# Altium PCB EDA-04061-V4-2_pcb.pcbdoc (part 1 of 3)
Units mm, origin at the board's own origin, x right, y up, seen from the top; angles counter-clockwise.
Board outline 105 x 56 mm, 6 copper layers (Top Layer, L2, L3, L4, L5, Bottom Layer), stack 1.58 mm thick; 213 components, 137 nets, 766 pads, 477 vias.
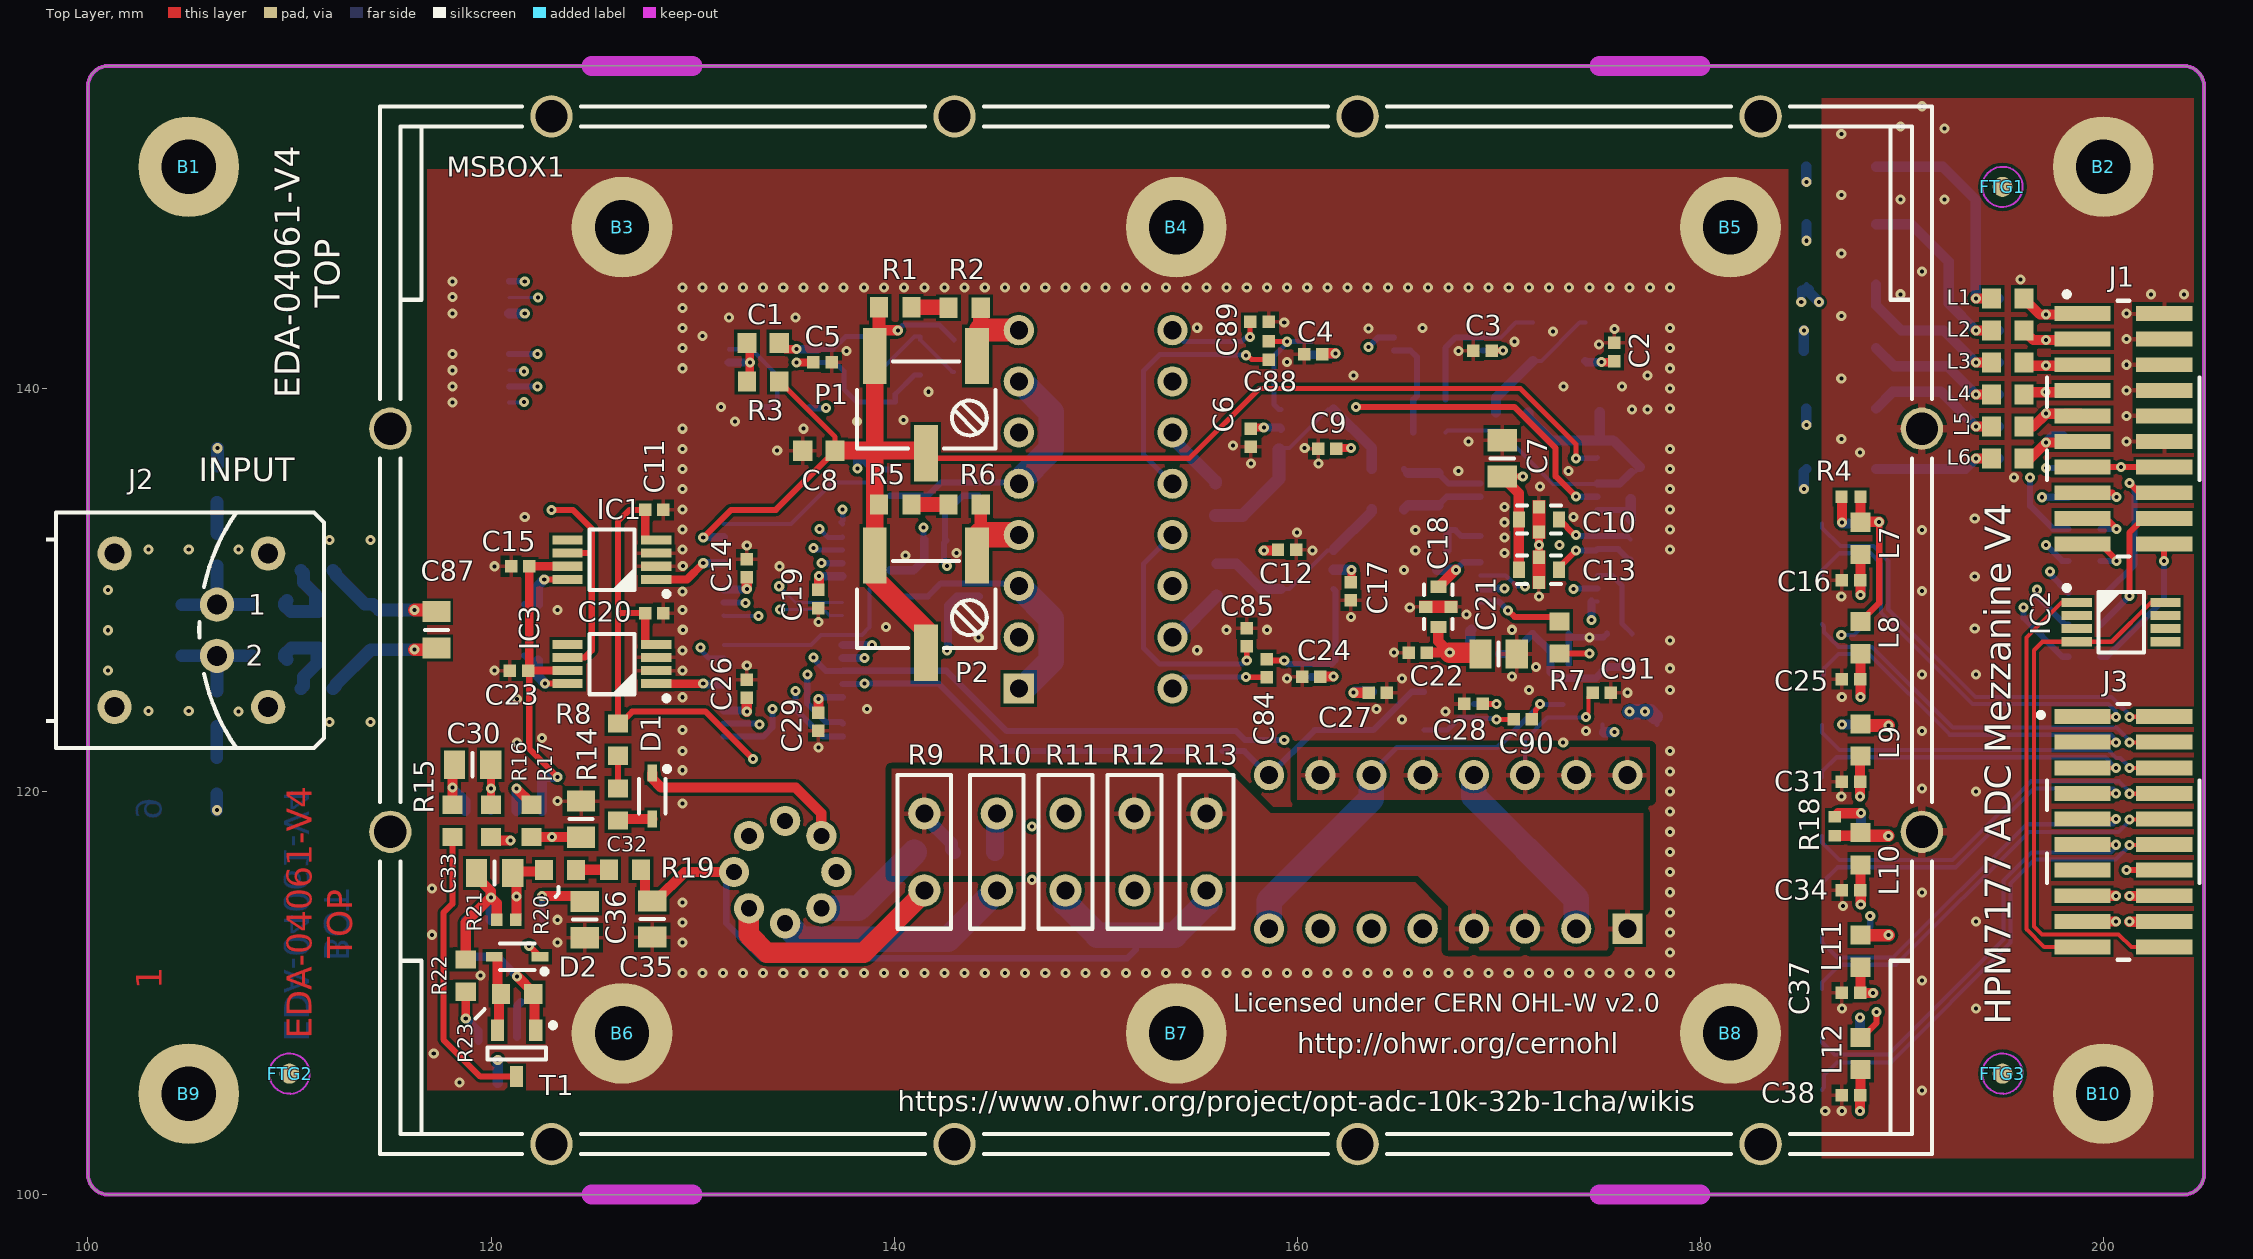
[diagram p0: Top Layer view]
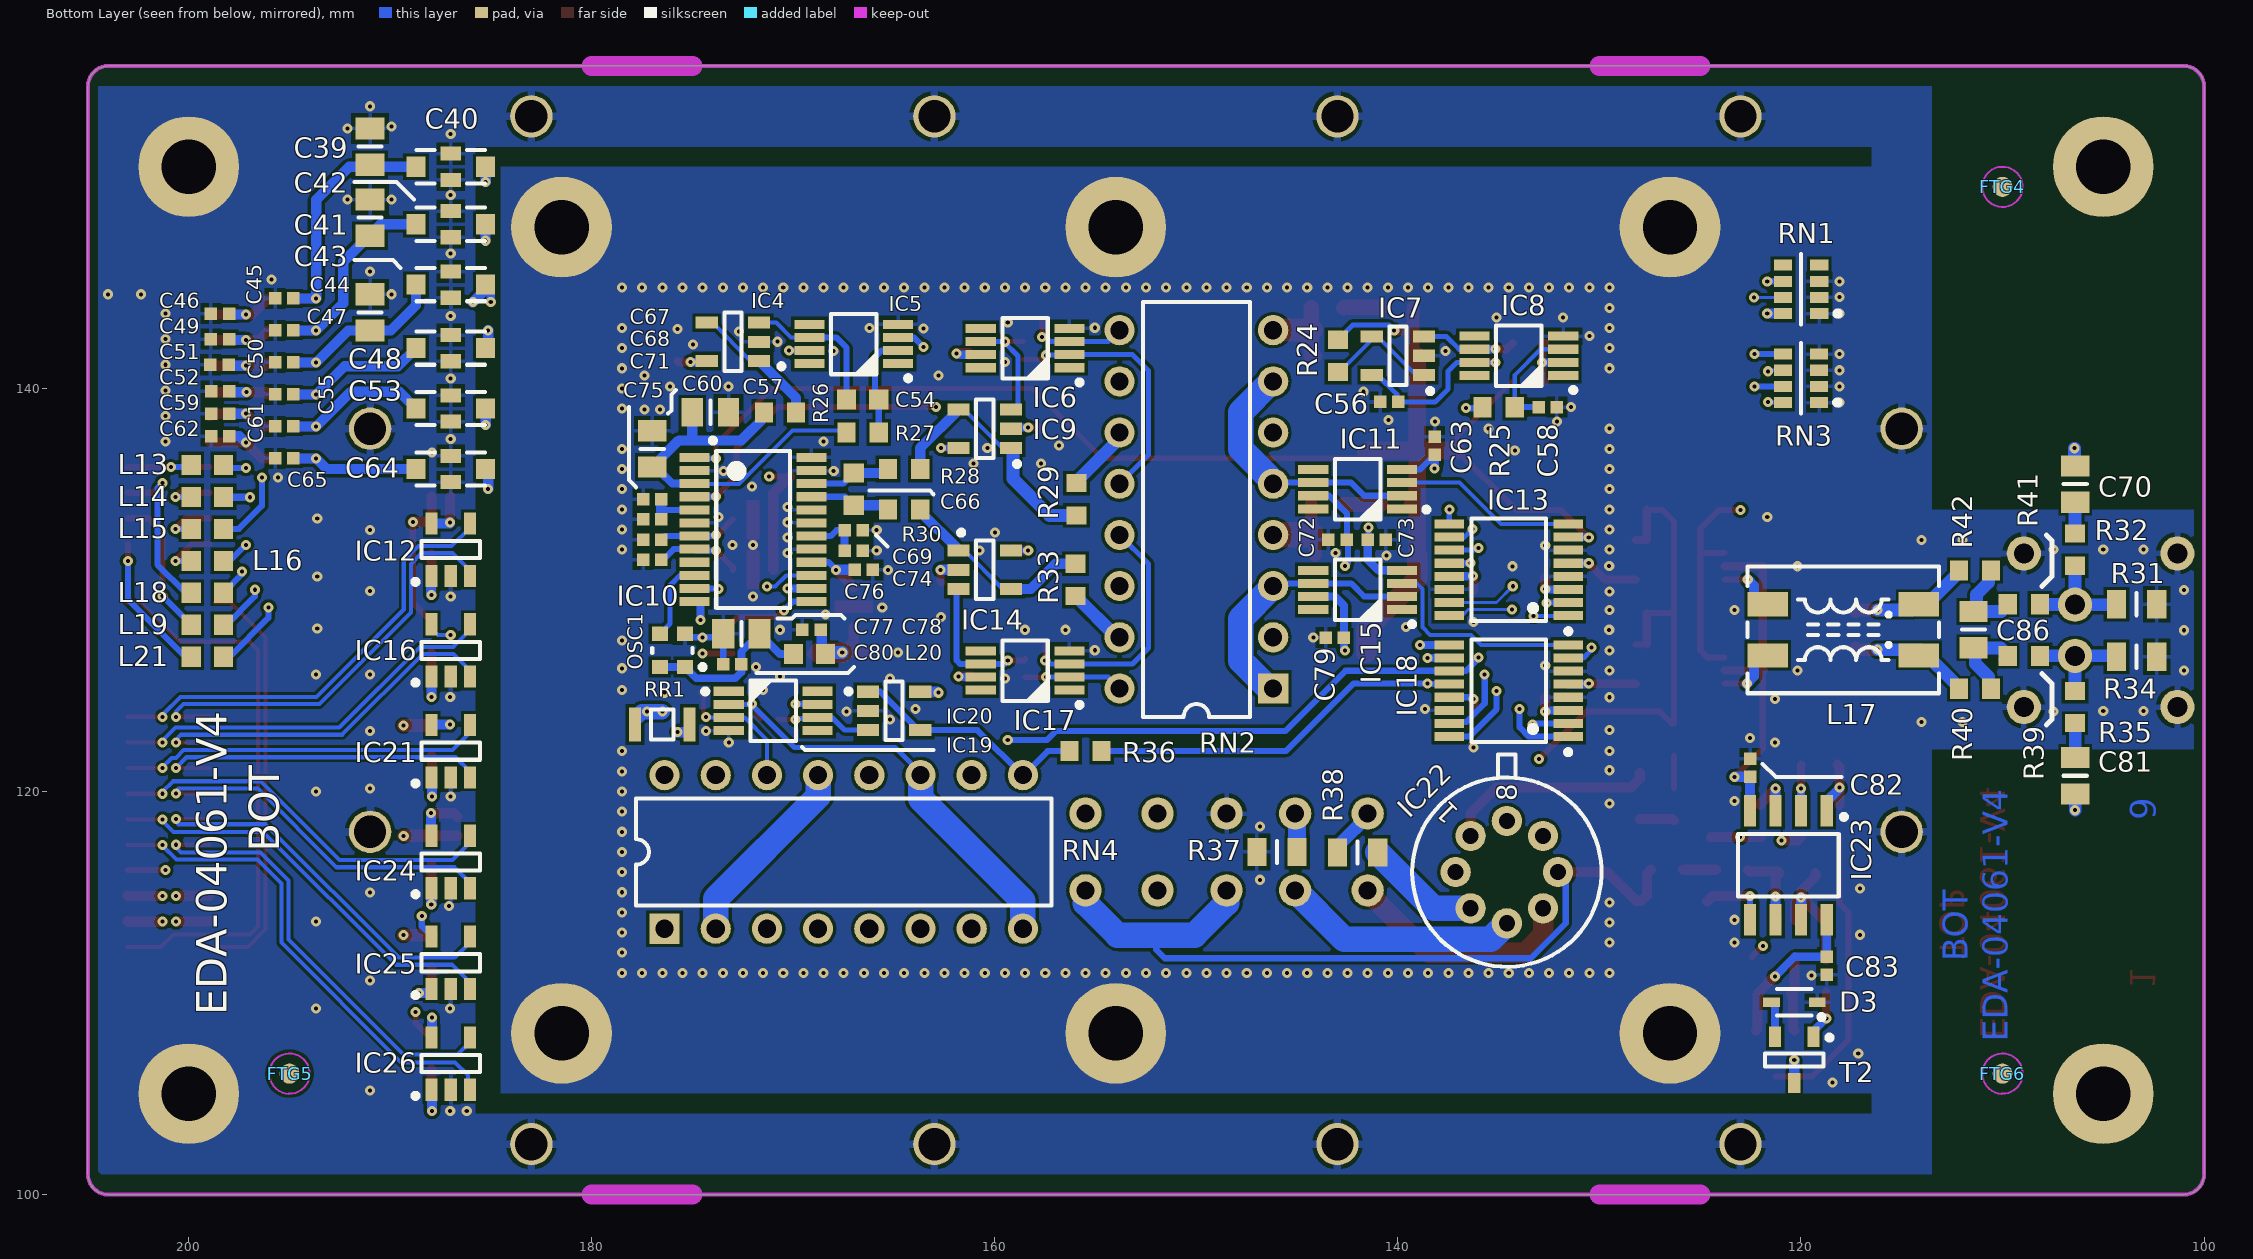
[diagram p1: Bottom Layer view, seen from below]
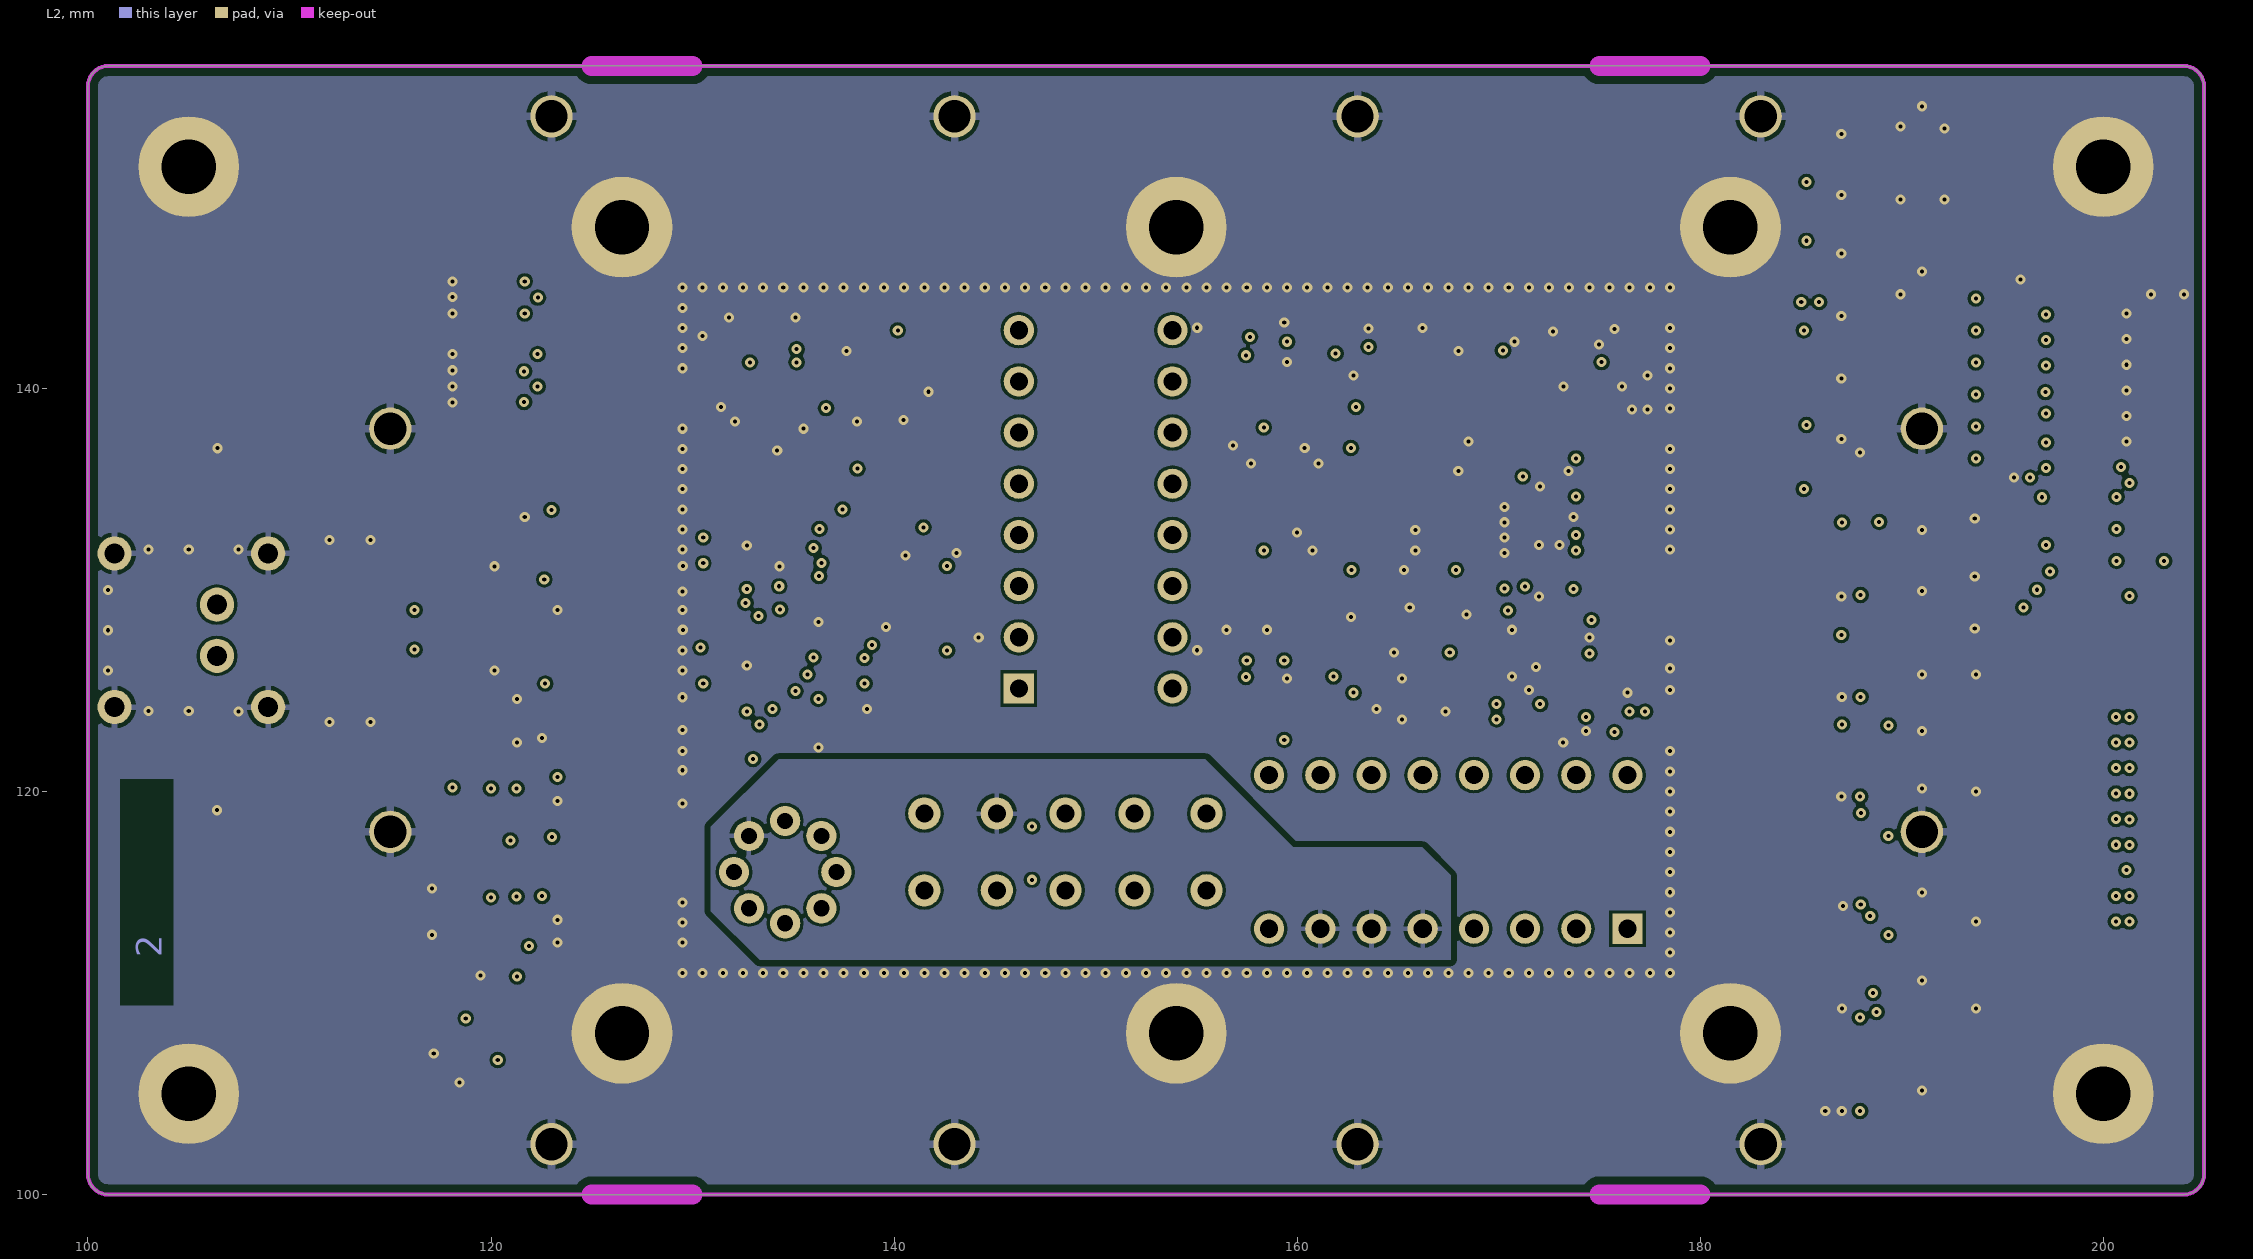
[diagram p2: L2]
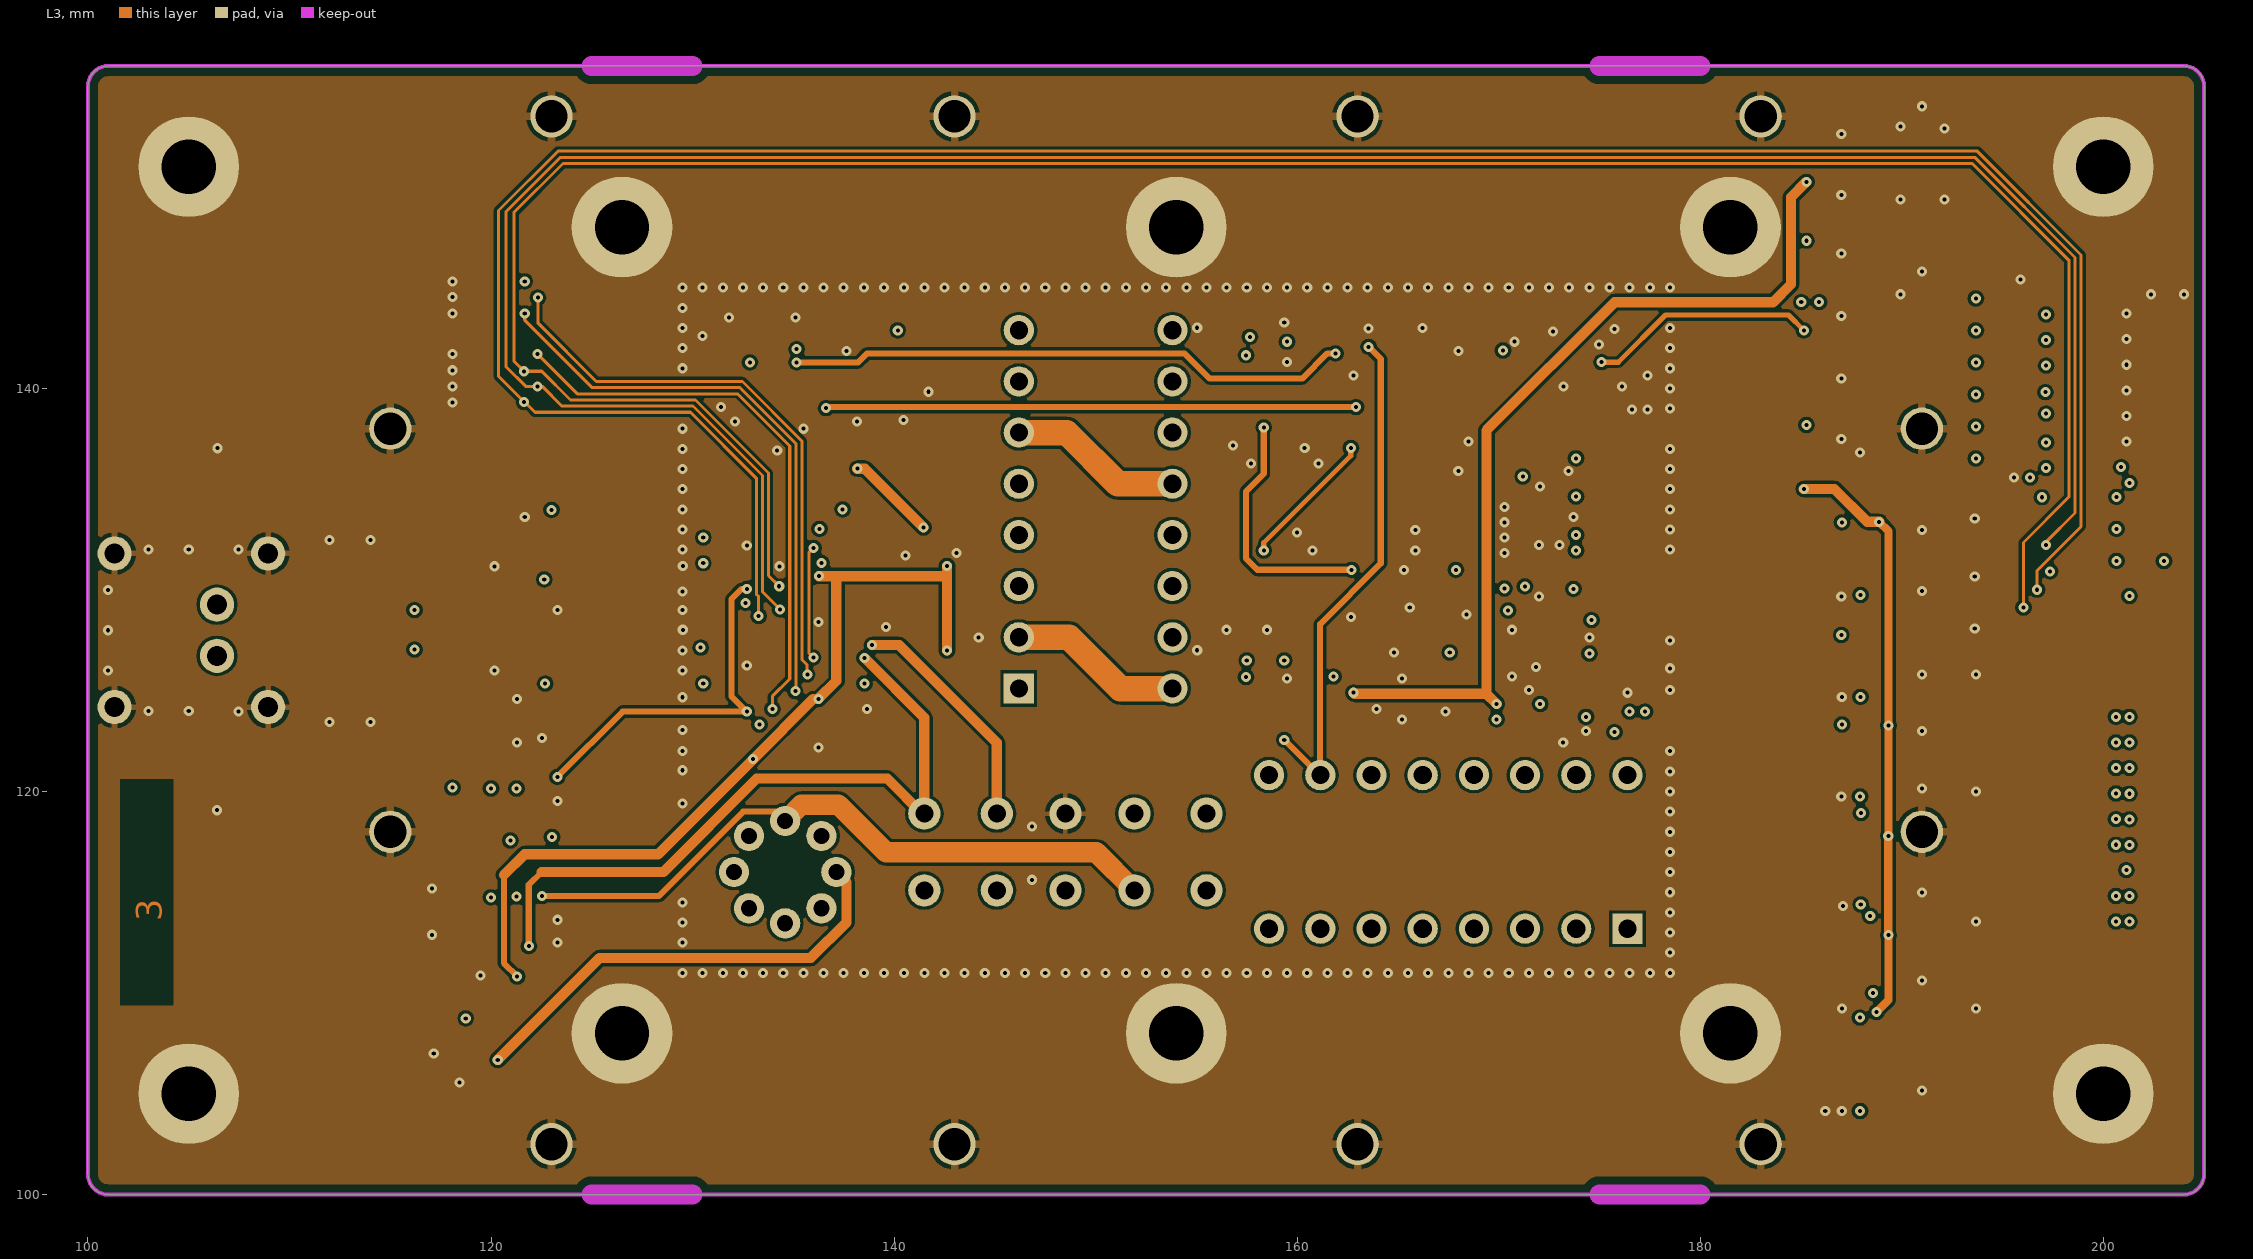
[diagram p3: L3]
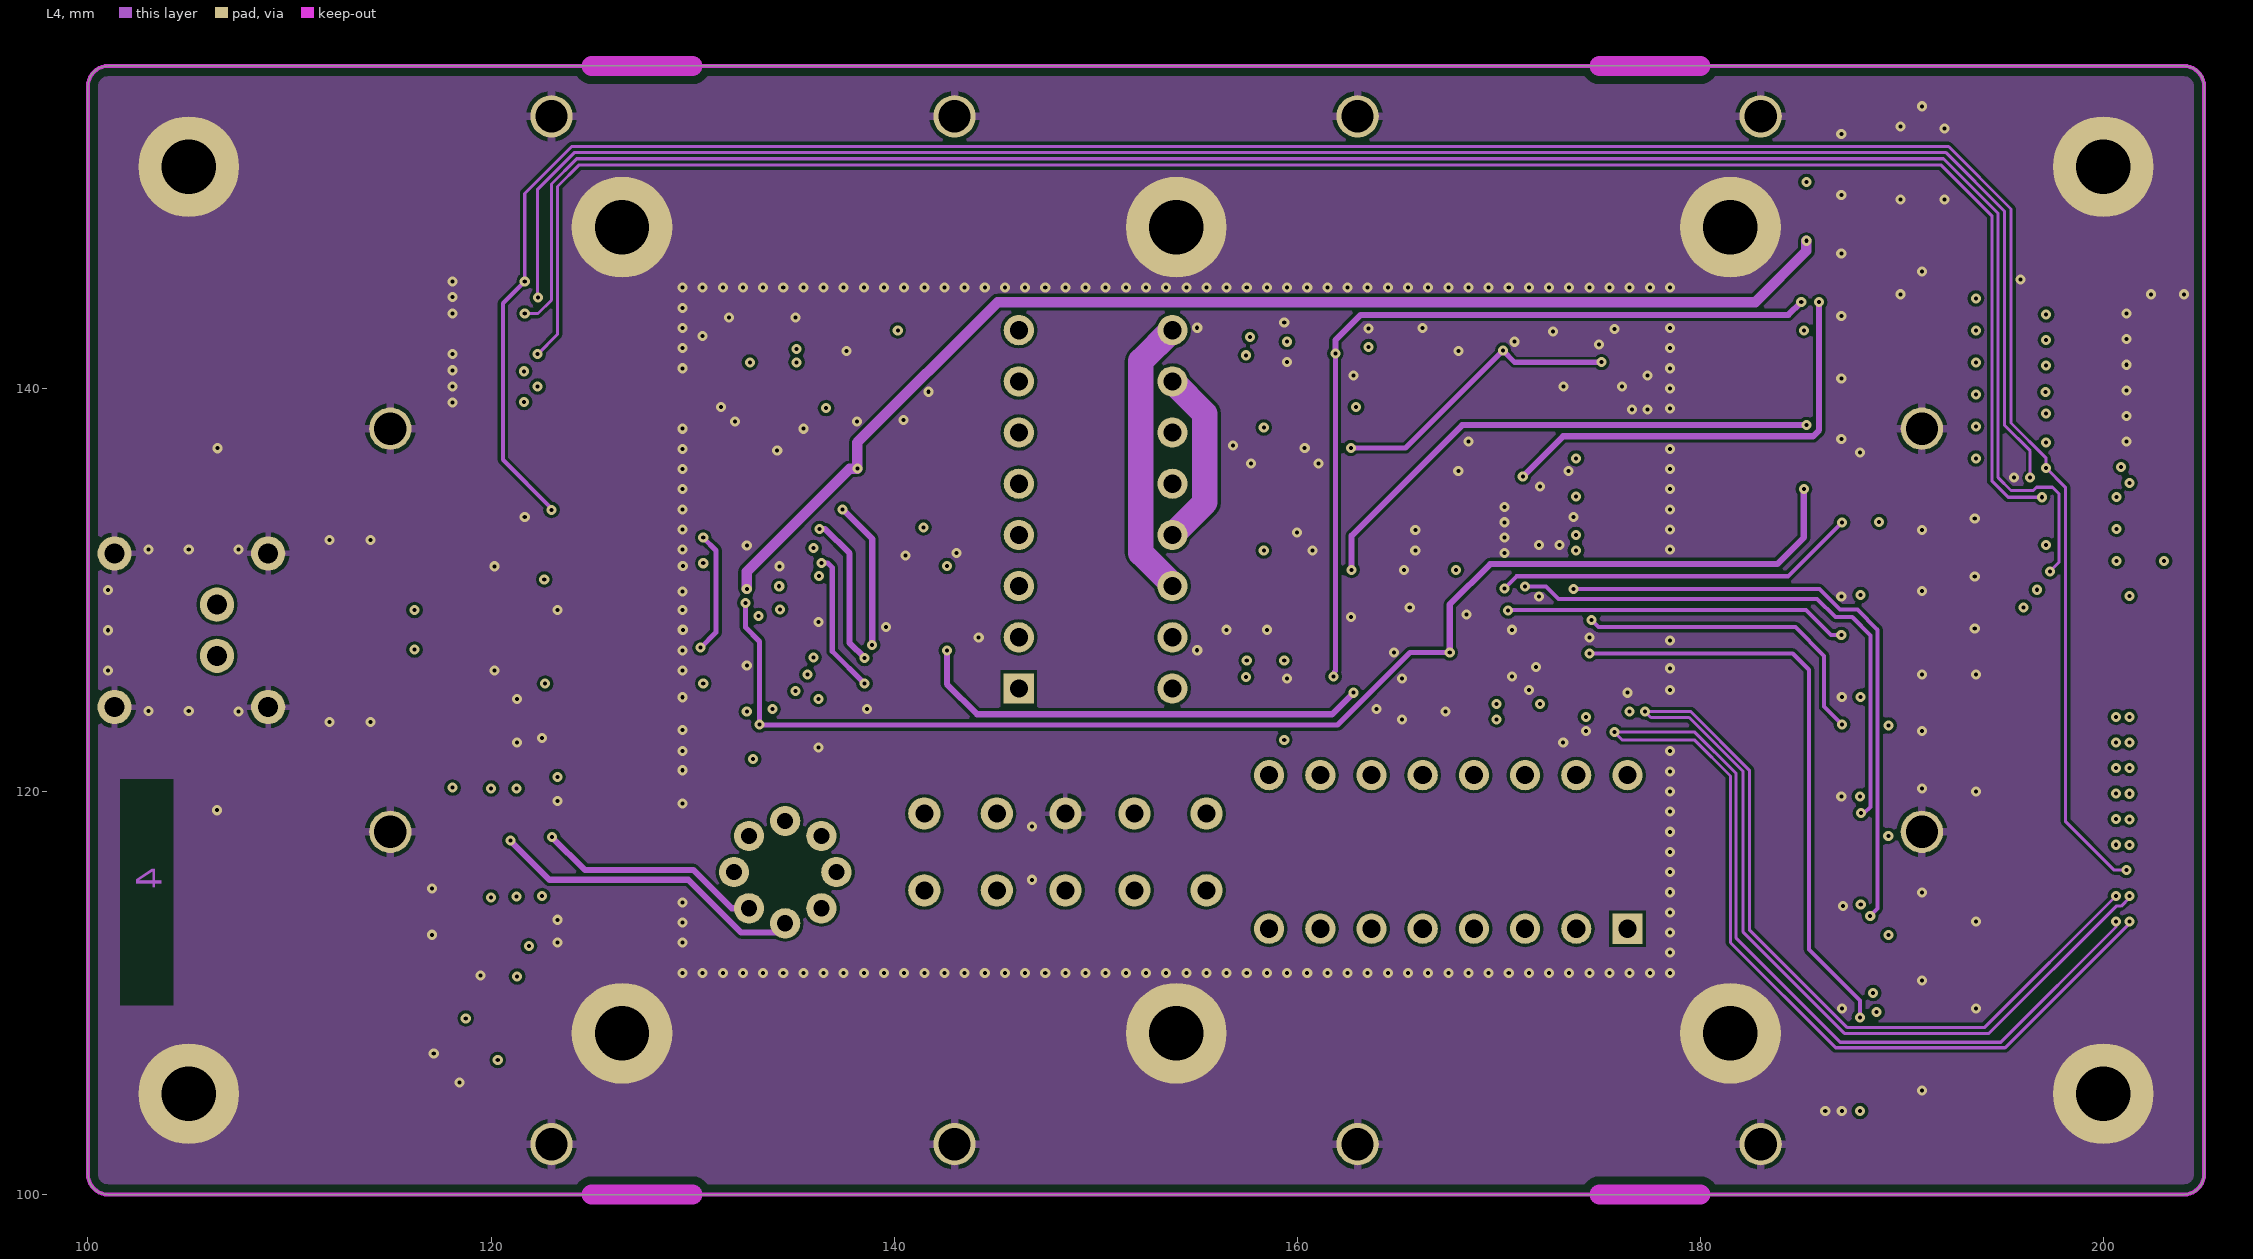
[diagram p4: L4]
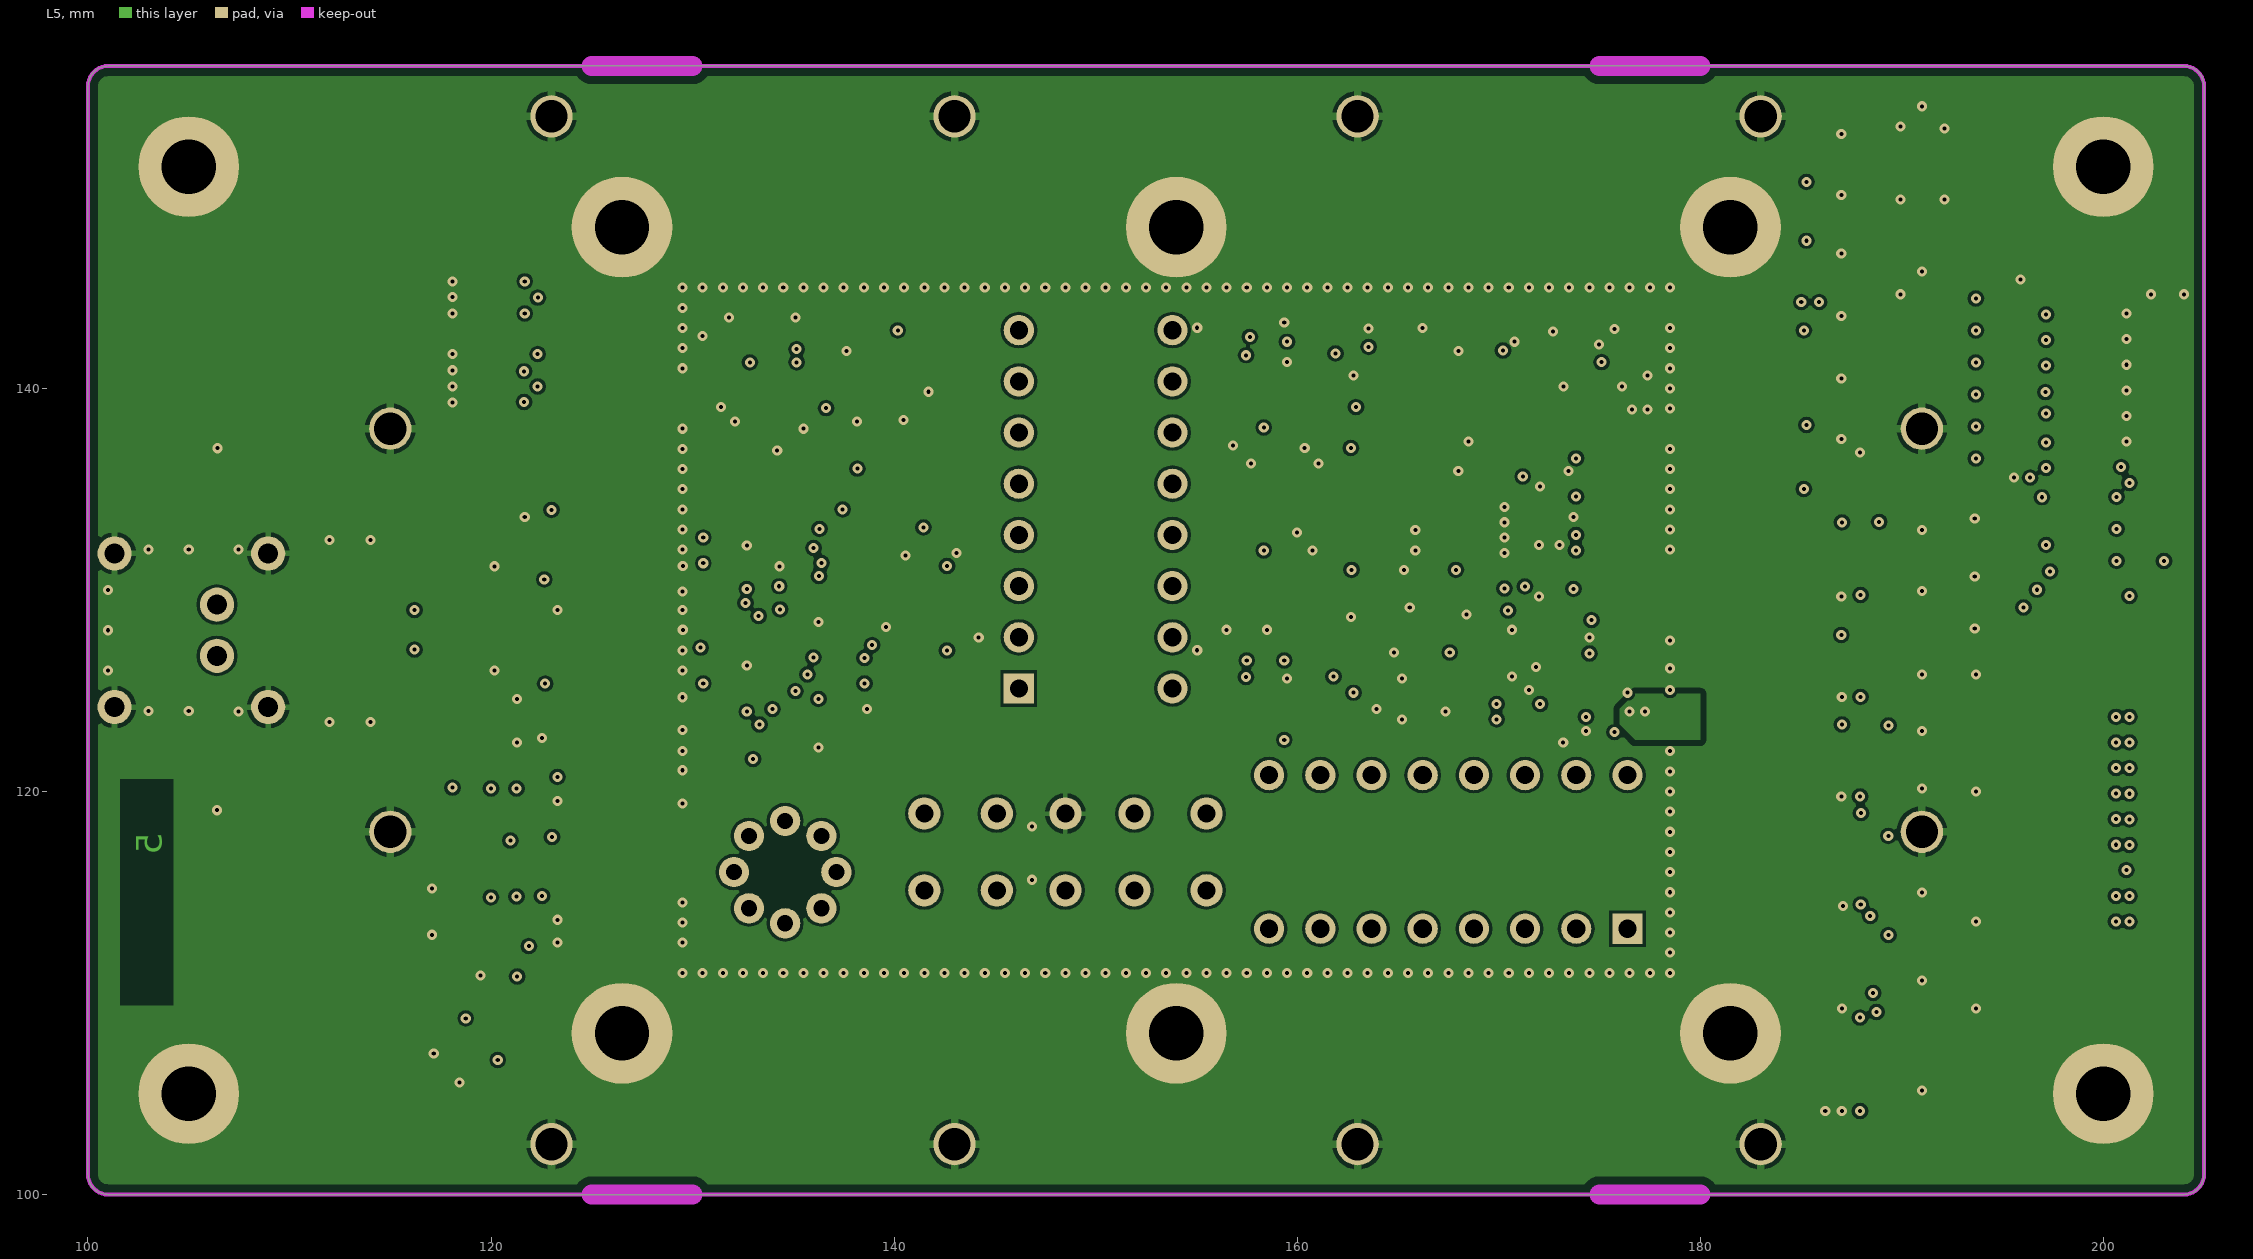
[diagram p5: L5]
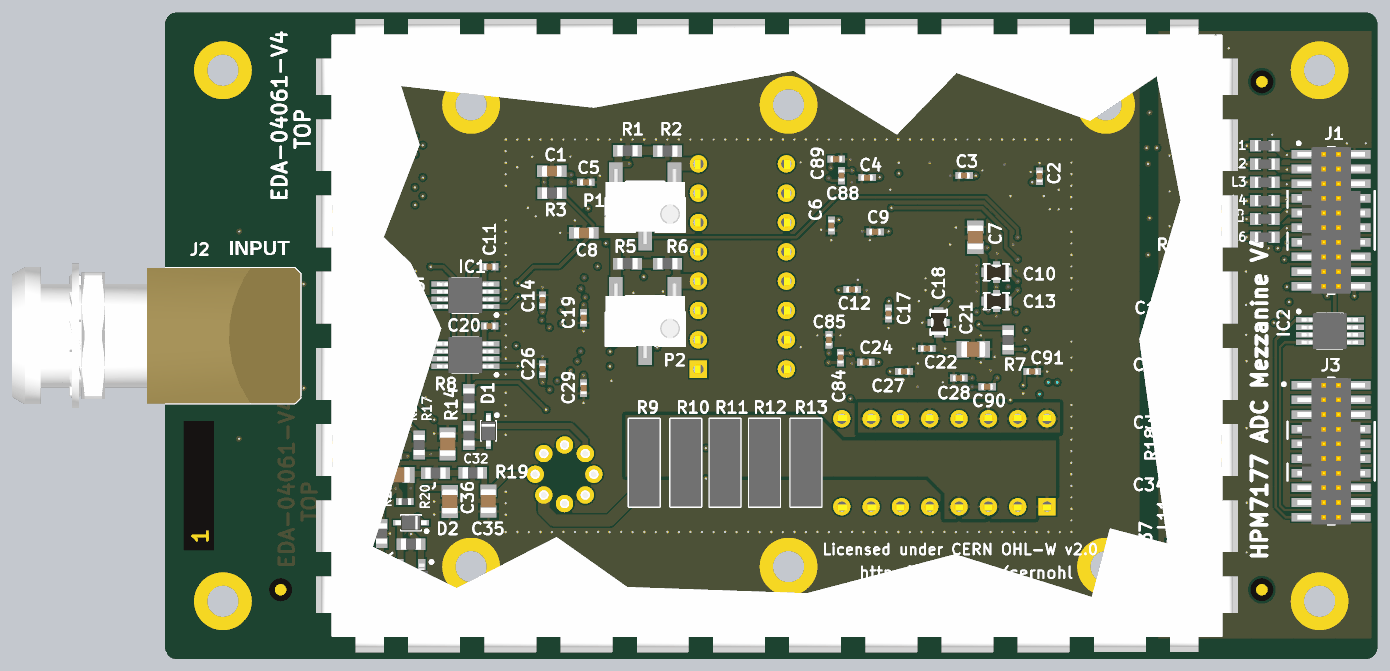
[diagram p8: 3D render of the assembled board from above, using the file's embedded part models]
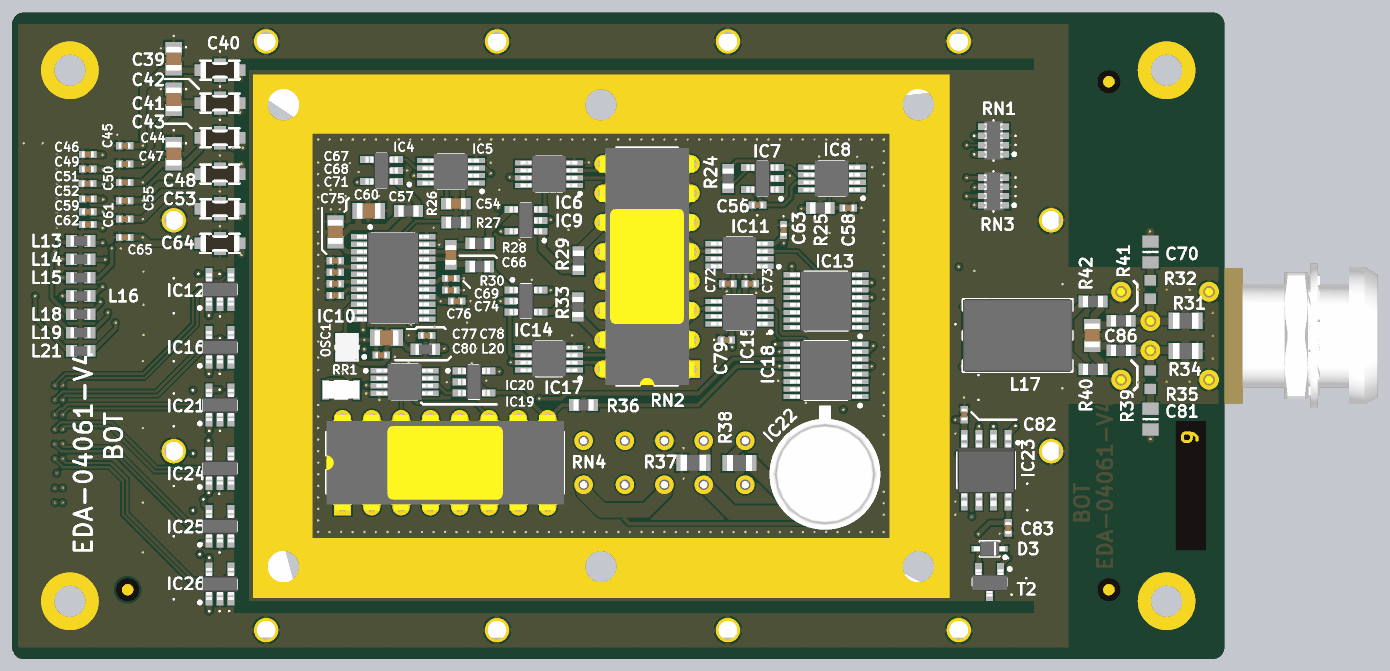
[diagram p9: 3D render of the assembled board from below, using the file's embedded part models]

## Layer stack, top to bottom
Top Solder: solder mask 0.01, Solder Resist, Dk 3.5
Top Layer: signal copper 0.035
Dielectric 1: prepreg 0.3, Dk 4.6
L2: signal copper 0.035
Dielectric 8: core 0.3, Dk 4.6
L3: signal copper 0.035
Dielectric 7: prepreg 0.17, Dk 4.6
L4: signal copper 0.035
Dielectric 6: core 0.3, Dk 4.6
L5: signal copper 0.035
Dielectric 5: prepreg 0.3, Dk 4.6
Bottom Layer: signal copper 0.035
Bottom Solder: solder mask 0.01, Solder Resist, Dk 3.5

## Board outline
100,101 100,155 cw(c101,155) 101,156 204,156 cw(c204,155) 205,155 205,101 cw(c204,101) 204,100 101,100 cw(c101,101)

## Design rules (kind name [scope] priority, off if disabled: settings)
Clearance Clearance_Spacers [InPadClass('Spacers')] p1: gap=0.5 ignorepadtopadclearanceinfootprint=FALSE
Clearance Clearance_Poly [InPolygon vs InPolygon] p2: gap=0.3 ignorepadtopadclearanceinfootprint=FALSE
Clearance Clearance_KeepOut [OnLayer('Keep-Out Layer') vs (InPadClass('DIN')) or InPolygon] p3: gap=0.4 ignorepadtopadclearanceinfootprint=FALSE except(0.1: Arc-THPad Track-THPad)
Clearance Clearance_Mires [OnLayer('Keep-Out Layer') vs HasFootprint('FIDUCIAL_TOP_S200-400') or HasFootprint('FIDUCIAL_TOP_C100-200') or HasFootprint('FIDUCIAL_TOP_S100-200')] p4: gap=0 ignorepadtopadclearanceinfootprint=FALSE except(4.9: Arc-SMDPad Track-SMDPad)
Clearance [All] p5: gap=0.15 ignorepadtopadclearanceinfootprint=FALSE
ComponentClearance ComponentClearance_Overlapping [InComponentClass('Overlapping') or InComponentClass('NotMounted') vs InComponentClass('Overlapping')] p1: gap=0 collisioncheckmode=3 verticalgap=0 showdistances=FALSE
ComponentClearance [not InComponentClass('Overlapping')] p2: gap=0.2 collisioncheckmode=3 verticalgap=0.2 showdistances=FALSE
DiffPairsRouting [All] p1: maxlimit=0.152 minlimit=0.152 mostfreqgap=0.152 toplayer_minwidth=0.203 toplayer_maxwidth=0.203 toplayer_prefwidth=0.203 midlayer1_minwidth=0.203 midlayer1_maxwidth=0.203 midlayer1_prefwidth=0.203 midlayer2_minwidth=0.203 midlayer2_maxwidth=0.203 midlayer2_prefwidth=0.203 midlayer3_minwidth=0.203 midlayer3_maxwidth=0.203 midlayer3_prefwidth=0.203 midlayer4_minwidth=0.203 midlayer4_maxwidth=0.203 midlayer4_prefwidth=0.203 bottomlayer_minwidth=0.203 bottomlayer_maxwidth=0.203 bottomlayer_prefwidth=0.203 maxuncoupledlength=12.7
FabricationTestPointUsage TestPointUsage [All] p1: valid=0 allowmultiple=FALSE
FabricationTestpoint Testpoint [All] p1: side=3 testpointundercomponent=TRUE minsize=1.016 maxsize=2.54 preferedsize=1.524 minholesize=0 maxholesize=1.016 preferedholesize=0.813 testpointgrid=0.025 allowsidetop=TRUE allowsidebottom=TRUE usegrid=TRUE gridtolerance=0
Height [All] p1: minheight=0 maxheight=25 prefheight=10
HoleSize [All] p1: absolutevalues=TRUE maxlimit=5 minlimit=0.2 maxpercent=80.000 minpercent=20.000
HoleToHoleClearance [All] p1: gap=0.2 allowstackedmicrovias=TRUE
MinimumAnnularRing MinimumAnnularRing_Via [IsVia] p1: minimumring=0.15
MinimumAnnularRing [All] p2: minimumring=0.25
MinimumSolderMaskSliver [All] p1: minsoldermaskwidth=0.2
PermittedLayers [All] p1: toplayerpermitted=TRUE bottomlayerpermitted=TRUE
PlaneClearance [All] p1: clearance=0.5
PlaneConnect PlaneConnect_Direct [InPadClass('Mounting') or IsVia] p1: planeconnectstyle=Direct reliefexpansion=0.508 reliefentries=4 reliefconductorwidth=0.254 reliefairgap=0.254
PlaneConnect "PlaneConnect_0 > 0.5" [AsMM(HoleDiameter)<0.5] p2: planeconnectstyle=Relief reliefexpansion=0.3 reliefentries=4 reliefconductorwidth=0.2 reliefairgap=0.2
PlaneConnect "PlaneConnect_0.5 > 1" [(AsMM(HoleDiameter)>=0.5) and (AsMM(HoleDiameter)<1)] p3: planeconnectstyle=Relief reliefexpansion=0.3 reliefentries=4 reliefconductorwidth=0.25 reliefairgap=0.2
PlaneConnect "PlaneConnect_1 > 1.5" [(AsMM(HoleDiameter)>=1) and (AsMM(HoleDiameter)<1.5)] p4: planeconnectstyle=Relief reliefexpansion=0.3 reliefentries=4 reliefconductorwidth=0.3 reliefairgap=0.2
PlaneConnect "PlaneConnect_1.5 > 2" [(AsMM(HoleDiameter)>=1.5) and (AsMM(HoleDiameter)<2)] p5: planeconnectstyle=Relief reliefexpansion=0.3 reliefentries=4 reliefconductorwidth=0.4 reliefairgap=0.2
PlaneConnect [All] p6: planeconnectstyle=Relief reliefexpansion=0.3 reliefentries=4 reliefconductorwidth=0.5 reliefairgap=0.2
PolygonConnect PolygonConnect_Direct [InPadClass('Mounting') or IsVia] p1: connectstyle=Direct reliefconductorwidth=0.254 reliefentries=4 polygonreliefangle="90 Angle" airgapwidth=0.254
PolygonConnect "PolygonConnect_0 > 0.5" [AsMM(HoleDiameter)<0.5] p2: connectstyle=Relief reliefconductorwidth=0.2 reliefentries=4 polygonreliefangle="90 Angle" airgapwidth=0.2
PolygonConnect "PolygonConnect_0.5 > 1" [(AsMM(HoleDiameter)>=0.5) and (AsMM(HoleDiameter)<1)] p3: connectstyle=Relief reliefconductorwidth=0.25 reliefentries=4 polygonreliefangle="90 Angle" airgapwidth=0.2
PolygonConnect "PolygonConnect_1 > 1.5" [(AsMM(HoleDiameter)>=1) and (AsMM(HoleDiameter)<1.5)] p4: connectstyle=Relief reliefconductorwidth=0.3 reliefentries=4 polygonreliefangle="90 Angle" airgapwidth=0.2
PolygonConnect "PolygonConnect_1.5 > 2" [(AsMM(HoleDiameter)>=1.5) and (AsMM(HoleDiameter)<2)] p5: connectstyle=Relief reliefconductorwidth=0.4 reliefentries=4 polygonreliefangle="90 Angle" airgapwidth=0.2
PolygonConnect [All] p6: connectstyle=Relief reliefconductorwidth=0.5 reliefentries=4 polygonreliefangle="90 Angle" airgapwidth=0.2
RoomDefinition "Voltage Reference" [InComponentClass('Voltage Reference')] p1: confinementstyle=ConfineIn formatcopy=TRUE lockcomponents=FALSE outline 116.999,104.457 178.118,104.457 178.118,126.047 116.999,126.047
RoomDefinition "Input Section" [InComponentClass('Input Section')] p2: confinementstyle=ConfineIn formatcopy=TRUE lockcomponents=FALSE outline 101.282,118.745 168.116,118.745 168.116,145.097 101.282,145.097
RoomDefinition Connectors [InComponentClass('Connectors')] p3: confinementstyle=ConfineIn formatcopy=TRUE lockcomponents=FALSE outline 100.33,100.33 205.264,100.33 205.264,155.734 100.33,155.734
RoomDefinition ADC [InComponentClass('ADC')] p4: confinementstyle=ConfineIn formatcopy=TRUE lockcomponents=FALSE outline 163.512,116.999 188.754,116.999 188.754,144.463 163.512,144.463
RoomDefinition top [InComponentClass('top')] p5: confinementstyle=ConfineIn formatcopy=TRUE lockcomponents=FALSE outline 86.421,121.45 86.421,134.55 112.021,134.55 112.021,121.45
RoutingVias RoutingVias_NoNet [Not IsElectrical] p1: holewidth=0 width=0 viastyle="Through Hole" minholewidth=0 minwidth=0 maxholewidth=0 maxwidth=0
RoutingVias [All] p2: holewidth=0.2 width=0.5 viastyle="Through Hole" minholewidth=0.2 minwidth=0.5 maxholewidth=0.2 maxwidth=0.5
SilkToSilkClearance [All] p1: silktosilkclearance=0.2
SilkToSolderMaskClearance SilkscreenOverComponentPads [IsPad] p1: minsilkscreentomaskgap=0.15 clearancetoexposedcopper=TRUE
SolderMaskExpansion SolderMaskExpansion_Vias [IsVia] p1: expansion=0 istentingtop=TRUE
SolderMaskExpansion [All] p2: expansion=0 istentingtop=FALSE
SupplyNets "Schematic Supply Nets_7" [InNet('REF_GND')] p1: voltage=0.000
SupplyNets "Schematic Supply Nets_6" [InNet('+15V')] p2: voltage=0.000
SupplyNets "Schematic Supply Nets_5" [InNet('-15V')] p3: voltage=0.000
SupplyNets "Schematic Supply Nets_4" [InNet('+5V')] p4: voltage=0.000
SupplyNets "Schematic Supply Nets_3" [InNet('+7.5V')] p5: voltage=0.000
SupplyNets "Schematic Supply Nets_2" [InNet('2V5_digital')] p6: voltage=0.000
SupplyNets "Schematic Supply Nets_1" [InNet('GND')] p7: voltage=0.000
SupplyNets "Schematic Supply Nets" [InNet('-2.5V')] p8: voltage=0.000
ViasUnderSMD [All] p1: allowed=FALSE
Width [All] p1: maxlimit=2.54 minlimit=0.152 preferedwidth=0.305
18 further rules are at their usual default settings.

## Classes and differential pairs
component class NotMounted: C70 C81 R32 R35
pad class Mounting: B1-1 B2-1 B3-1 B4-1 B5-1 B6-1 B7-1 B8-1 B9-1 B10-1
pad class Spacers: B1-1 B2-1 B9-1 B10-1
component class ADC: 30 C7 C10 C13 C18 C21 C22 C54 C57 C60 C67 C68 C69 C71 C74 C75 C76 C77 C78 C80 IC4 IC5 IC10 L20 OSC1 R4 R7 R18 R26 R27
component class Connectors: B1 B2 B3 B4 B5 B6 B7 B8 B9 B10 C2 C3 C4 C5 C6 C9 C11 C12 C14 C15 C16 C17 C19 C20 C23 C24 C25 C26 C27 C28 C29 C31 C34 C37 C38 C39 C40 C41 C42 C43 C44 C45 C46 C47 C48 C49 C50 C51 C52 C53 C55 C56 C59 C61 C62 C63 C64 C65 C72 C73 C79 C82 C83 FTG1 FTG2 FTG3 FTG4 FTG5 FTG6 IC2 IC12 IC16 IC21 IC24 IC25 IC26 J1 J3 L1 L2 L3 L4 L5 L6 L7 L8 L9 L10 L11 L12 L13 L14 L15 L16 L18 L19 L21 MSBOX1 RN1 RN3 RR1
component class "Input Section": C1 C8 C58 C66 C70 C81 C84 C85 C86 C87 C88 C89 IC1 IC3 IC6 IC7 IC8 IC9 IC11 IC13 IC14 IC15 IC17 IC18 L17 P1 P2 R1 R2 R3 R5 R6 R24 R25 R28 R29 R30 R31 R32 R33 R34 R35 R39 R40 R41 R42 RN2
component class top: J2
component class "Voltage Reference": C30 C32 C33 C35 C36 C90 C91 D1 D2 D3 IC19 IC20 IC22 IC23 R8 R9 R10 R11 R12 R13 R14 R15 R16 R17 R19 R20 R21 R22 R23 R36 R37 R38 RN4 T1 T2
differential pair CS_DIFF: +CS_DIFF_P -CS_DIFF_N
differential pair DIN_DIFF: +DIN_DIFF_P -DIN_DIFF_N
differential pair DOUT_DIFF: +DOUT_DIFF_P -DOUT_DIFF_N
differential pair SCK_DIFF: +SCK_DIFF_P -SCK_DIFF_N
differential pair SCK_FB_DIFF: +SCK_FB_DIFF_P -SCK_FB_DIFF_N
differential pair SYNC_DIFF: +SYNC_DIFF_P -SYNC_DIFF_N

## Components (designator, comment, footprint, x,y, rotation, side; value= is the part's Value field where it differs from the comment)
B1 "Plated Hole" MTG270_500 105,151 r0 top
B2 "Plated Hole" MTG270_500 200,151 r0 top
B3 "Plated Hole" MTG270_500 126.5,148 r0 top
B4 "Plated Hole" MTG270_500 154,148 r0 top
B5 "Plated Hole" MTG270_500 181.5,148 r0 top
B6 "Plated Hole" MTG270_500 126.5,108 r0 top
B7 "Plated Hole" MTG270_500 154,108 r0 top
B8 "Plated Hole" MTG270_500 181.5,108 r0 top
B9 "Plated Hole" MTG270_500 105,105 r0 top
B10 "Plated Hole" MTG270_500 200,105 r0 top
C1 "10nF" CAPC1608X87N 133.5,142.259 r180 top
C2 "100nF" CAPC1005X55N 175.743,141.809 r90 top
C3 "100nF" CAPC1005X55N 169.2,141.879 r0 top
C4 "100nF" CAPC1005X55N 160.8,141.7 r0 top
C5 "100nF" CAPC1005X55N 136.45,141.294 r0 top
C6 "100nF" CAPC1005X55N 157.709,137.549 r270 top
C7 "10uF" CAPC2012X95N 170.18,136.525 r270 top
C8 "10nF" CAPC1608X87N 136.271,136.906 r0 top
C9 "100nF" CAPC1005X55N 161.5,137 r0 top
C10 "2.2uF" CAPC_MURATA_NFM21PC_0805 172,133.5 r0 top
C11 "100nF" CAPC1005X55N 128.1,133.975 r180 top
C12 "100nF" CAPC1005X55N 159.5,132 r0 top
C13 "2.2uF" CAPC_MURATA_NFM21PC_0805 172,131 r0 top
C14 "100nF" CAPC1005X55N 132.69,131.072 r90 top
C15 "100nF" CAPC1005X55N 121.445,131.175 r0 top
C16 "100nF" CAPC1005X55N 187.484,130.493 r180 top
C17 "100nF" CAPC1005X55N 162.662,129.929 r270 top
C18 "2.2uF" CAPC_MURATA_NFM21PC_0805 167.005,129.159 r270 top
C19 "100nF" CAPC1005X55N 136.246,129.548 r270 top
C20 "100nF" CAPC1005X55N 128.1,128.85 r180 top
C21 "10uF" CAPC2012X95N 170,126.822 r180 top
C22 "100nF" CAPC1005X55N 165.982,126.892 r180 top
C23 "100nF" CAPC1005X55N 121.385,126 r0 top
C24 "100nF" CAPC1005X55N 160.7,125.7 r0 top
C25 "100nF" CAPC1005X55N 187.484,125.571 r180 top
C26 "100nF" CAPC1005X55N 132.69,125.103 r90 top
C27 "100nF" CAPC1005X55N 164,124.9 r0 top
C28 "100nF" CAPC1005X55N 168.75,124.341 r0 top
C29 "100nF" CAPC1005X55N 136.246,123.452 r270 top
C30 "47nF" CAPC2012X135N 119.089,121.331 r180 top
C31 "100nF" CAPC1005X55N 187.484,120.491 r180 top
C32 "47nF" CAPC2012X135N 124.467,118.626 r270 top
C33 "47nF" CAPC2012X135N 120.177,115.951 r0 top
C34 "100nF" CAPC1005X55N 187.484,115.094 r180 top
C35 "47nF" CAPC2012X135N 128,113.672 r90 top
C36 "47nF" CAPC2012X135N 124.65,113.64 r90 top
C37 "100nF" CAPC1005X55N 187.484,110.014 r180 top
C38 "100nF" CAPC1005X55N 187.484,104.934 r180 top
C39 "10uF" CAPC2012X95N 191,152 r90 bottom
C40 "22nF" CAPC_MURATA_NFM3DC_1206 187,151 r0 bottom
C41 "10uF" CAPC2012X95N 191,148.472 r90 bottom
C42 "22nF" CAPC_MURATA_NFM3DC_1206 187,148.15 r0 bottom
C43 "22nF" CAPC_MURATA_NFM3DC_1206 187,145.15 r0 bottom
C44 "10uF" CAPC2012X95N 191,143.772 r90 bottom
C45 "100nF" CAPC1005X55N 195.262,144.463 r0 bottom
C46 "100nF" CAPC1005X55N 198.45,143.715 r180 bottom
C47 "100nF" CAPC1005X55N 195.262,142.875 r0 bottom
C48 "22nF" CAPC_MURATA_NFM3DC_1206 187,142 r0 bottom
C49 "100nF" CAPC1005X55N 198.45,142.445 r180 bottom
C50 "100nF" CAPC1005X55N 195.262,141.287 r0 bottom
C51 "100nF" CAPC1005X55N 198.476,141.175 r180 bottom
C52 "100nF" CAPC1005X55N 198.438,139.859 r180 bottom
C53 "22nF" CAPC_MURATA_NFM3DC_1206 187,139 r0 bottom
C54 "10nF" CAPC1608X87N 166.561,139.45 r180 bottom
C55 "100nF" CAPC1005X55N 195.262,139.7 r0 bottom
C56 "1uF" CAPC1005X55N 140.437,139.327 r180 bottom
C57 "47nF" CAPC2012X135N 174.115,138.819 r0 bottom
C58 "1uF" CAPC1005X55N 132.563,139.073 r0 bottom
C59 "100nF" CAPC1005X55N 198.438,138.748 r180 bottom
C60 "47nF" CAPC2012X135N 177,137 r270 bottom
C61 "100nF" CAPC1005X55N 195.262,138.112 r0 bottom
C62 "100nF" CAPC1005X55N 198.438,137.636 r180 bottom
C63 "100nF" CAPC1005X55N 138.176,137.16 r90 bottom
C64 "22nF" CAPC_MURATA_NFM3DC_1206 187,136 r0 bottom
C65 "100nF" CAPC1005X55N 195.262,136.525 r0 bottom
C66 "10nF" CAPC1608X87N 167,135 r270 bottom
C67 "100nF" CAPC1005X55N 177,134.5 r180 bottom
C68 "1uF" CAPC1005X55N 177,133.5 r180 bottom
C69 "1uF" CAPC1005X55N 167.005,132.969 r180 bottom
C70 "1nF" CAPC2012X135N 106.394,135.255 r270 bottom
C71 "100nF" CAPC1005X55N 177,132.5 r180 bottom
C72 "100nF" CAPC1005X55N 143,132.5 r0 bottom
C73 "100nF" CAPC1005X55N 141.05,132.5 r0 bottom
C74 "100nF" CAPC1005X55N 167.005,131.953 r180 bottom
C75 "100nF" CAPC1005X55N 177,131.5 r180 bottom
C76 "100nF" CAPC1005X55N 166.5,131 r0 bottom
C77 "10uF" CAPC2012X95N 172.575,127.825 r180 bottom
C78 "100nF" CAPC1005X55N 169.1,128.024 r0 bottom
C79 "100nF" CAPC1005X55N 143.129,127.635 r180 bottom
C80 "100nF" CAPC1005X55N 173.025,126.325 r0 bottom
C81 "1nF" CAPC2012X135N 106.394,120.781 r90 bottom
C82 "100nF" CAPC1005X55N 122.523,121.175 r270 bottom
C83 "100nF" CAPC1005X55N 118.72,111.349 r90 bottom
C84 "100pF" CAPC1005X55N 158.5,126.114 r90 top
C85 "100pF" CAPC1005X55N 157.5,127.65 r270 top
C86 "47nF" CAPC2012X135N 111.442,128.032 r270 bottom
C87 "47nF" CAPC2012X135N 117.287,128.024 r270 top
C88 "100pF" CAPC1005X55N 158.582,141.879 r90 top
C89 "100pF" CAPC1005X55N 158.132,143.3 r180 top
C90 "100pF" CAPC1005X55N 171.196,123.579 r180 top
C91 "100pF" CAPC1005X55N 175.108,124.9 r180 top
D1 "1N4148WS" SODFL2512X100N 128,119.769 r270 top
D2 "1N4148WS" SODFL2512X100N 121.298,111.799 r180 top
D3 "1N4148WS" SODFL2512X100N 120.332,109.537 r0 bottom
FTG1 "Use only in PCB" FIDUCIAL_TOP_C100-200 195,150 r0 top
FTG2 "Use only in PCB" FIDUCIAL_TOP_C100-200 110,106 r0 top
FTG3 "Use only in PCB" FIDUCIAL_TOP_C100-200 195,106 r0 top
FTG4 "Use only in PCB" FIDUCIAL_TOP_C100-200 110,150 r180 bottom
FTG5 "Use only in PCB" FIDUCIAL_TOP_C100-200 195,106 r180 bottom
FTG6 "Use only in PCB" FIDUCIAL_TOP_C100-200 110,106 r180 bottom
IC1 "ADG1419BRMZ" SOP65P490X110-8N 126,131.5 r180 top
IC2 "DS18B20U+" SOP65P490X110-8N 200.889,128.405 r0 top
IC3 "ADG1419BRMZ" SOP65P490X110-8N 126,126.325 r180 top
IC4 "AD8065ART" SOT95P280X145-5N 173,142.313 r0 bottom
IC5 "ADA4522-1ARMZ" SOP65P490X110-8N 167,142.204 r0 bottom
IC6 "OPA388IDGK" SOP65P490X110-8N 158.5,142 r0 bottom
IC7 "AD8065ART" SOT95P280X145-5N 140,141.619 r0 bottom
IC8 "ADA4522-1ARMZ" SOP65P490X110-8N 134,141.619 r0 bottom
IC9 "AD8065ART" SOT95P280X145-5N 160.5,138 r0 bottom
IC10 "AD7177-2BRUZ" SOP65P640X120-24N 172,133 r180 bottom
IC11 "OPA189IDGK" SOP65P490X110-8N 142,135 r0 bottom
IC12 "SN65LVDT2DBV" SOT95P280X145-5N 187,132 r90 bottom
IC13 "ADG1408YRUZ" SOP65P640X120-16N 134.497,131.001 r0 bottom locked
IC14 "AD8065ART" SOT95P280X145-5N 160.5,131 r180 bottom
IC15 "OPA189IDGK" SOP65P490X110-8N 142,130 r0 bottom
IC16 "SN65LVDT2DBV" SOT95P280X145-5N 187,127 r90 bottom
IC17 "OPA388IDGK" SOP65P490X110-8N 158.5,126 r0 bottom
IC18 "ADG1408YRUZ" SOP65P640X120-16N 134.5,125 r0 bottom
IC19 "ADA4522-1ARMZ" SOP65P490X110-8N 171,124 r180 bottom
IC20 "AD8065ART" SOT95P280X145-5N 165,124 r180 bottom
IC21 "SN65LVDT2DBV" SOT95P280X145-5N 187,122 r90 bottom
IC22 "ADR1000AHZ" TO-99 134.595,116 r90 bottom locked
IC23 "OPA2277U" SOIC127P600X175-8N 120.625,116.34 r270 bottom
IC24 "SN65LVDT2DBV" SOT95P280X145-5N 187,116.5 r90 bottom
IC25 "SN65LVDS1DBVT" SOT95P280X145-5N 187,111.5 r90 bottom
IC26 "SN65LVDS1DBVT" SOT95P280X145-5N 187,106.5 r90 bottom
J1 "Header 20" SAMTEC_FTSH-110-01-F-DV-K 201,138 r270 top
J2 "INPUT" LEMO_EXG.0B.302.HLN 105.131,128 r180 top locked
J3 "Header 20" SAMTEC_FTSH-110-01-F-DV-K 201,118 r270 top
L1 "1000R@100MHz" INDC1608X95N 195.262,144.463 r180 top
L2 "1000R@100MHz" INDC1608X95N 195.262,142.875 r180 top
L3 "1000R@100MHz" INDC1608X95N 195.262,141.287 r180 top
L4 "1000R@100MHz" INDC1608X95N 195.262,139.7 r180 top
L5 "1000R@100MHz" INDC1608X95N 195.262,138.112 r180 top
L6 "1000R@100MHz" INDC1608X95N 195.262,136.525 r180 top
L7 "1000R@100MHz" INDC1608X95N 187.96,132.556 r270 top
L8 "1000R@100MHz" INDC1608X95N 187.96,127.635 r270 top
L9 "1000R@100MHz" INDC1608X95N 187.96,122.555 r270 top
L10 "1000R@100MHz" INDC1608X95N 187.96,117.157 r270 top
L11 "1000R@100MHz" INDC1608X95N 187.96,112.078 r90 top
L12 "1000R@100MHz" INDC1608X95N 187.96,106.998 r90 top
L13 "1000R@100MHz" INDC1608X95N 199.072,136.207 r180 bottom
L14 "1000R@100MHz" INDC1608X95N 199.072,134.62 r180 bottom
L15 "1000R@100MHz" INDC1608X95N 199.072,133.032 r180 bottom
L16 "1000R@100MHz" INDC1608X95N 199.072,131.445 r180 bottom
L17 "2x10uH" IND_WURTH_WE-SL2 117.898,128.024 r0 bottom locked
L18 "1000R@100MHz" INDC1608X95N 199.072,129.857 r180 bottom
L19 "1000R@100MHz" INDC1608X95N 199.072,128.27 r180 bottom
L20 "1000R@100MHz" INDC1608X95N 169.2,126.822 r0 bottom
L21 "1000R@100MHz" INDC1608X95N 199.072,126.682 r180 bottom
MSBOX1 "Metal Screening Box 12 Pins" MSBOX_PERANCEA_PFL9T 153,128 r0 top locked
OSC1 "16MHz" OSC_ABRACON_AMPMD 176,127 r0 bottom
P1 "10" TRIM_BOURNS_3269W 141.58,139.2 r180 top
P2 "10" TRIM_BOURNS_3269W 141.58,129.294 r180 top
R1 "1" RESC1608X55N 140.056,144.026 r0 top
R2 "1" RESC1608X55N 143.5,144 r0 top
R3 "1k" RESC1608X55N 133.5,140.35 r0 top
R4 "10k" RESC1005X40N 187.484,134.62 r0 top
R5 "1" RESC1608X55N 140.056,134.239 r0 top
R6 "1" RESC1608X55N 143.5,134.239 r0 top
R7 "10" RESC1608X55N 173.025,127.643 r270 top
R8 "10" RESC1608X55N 126.3,122.575 r90 top
R9 "20k" RES_VISHAY_Z203 141.5,116.999 r90 top
R10 "120" RES_VISHAY_Z203 145.097,116.999 r270 top
R11 "1k" RES_VISHAY_Z203 148.5,116.999 r270 top
R12 "68k" RES_VISHAY_Z203 151.924,116.999 r90 top
R13 "12k" RES_VISHAY_Z203 155.5,117 r90 top
R14 "10" RESC1608X55N 126.3,119.354 r90 top
R15 "100" RESC1608X55N 118.087,118.54 r270 top
R16 "1k" RESC1608X55N 120,118.54 r90 top
R17 "1k" RESC1608X55N 122,118.54 r90 top
R18 "10k" RESC1005X40N 186.665,118.27 r270 top
R19 "1k" RESC1608X55N 126.645,116.115 r180 top
R20 "1k" RESC1608X55N 123.424,116.109 r180 top
R21 "330k" RESC1005X40N 120.752,113.634 r0 top
R22 "1k" RESC1608X55N 118.745,110.861 r90 top
R23 "100k" RESC1608X55N 121.298,109.956 r0 top
R24 "10" RESC1608X55N 142.977,141.613 r90 bottom
R25 "100" RESC1608X55N 135.001,139.065 r180 bottom
R26 "10" RESC1608X55N 170.663,138.808 r0 bottom
R27 "1k" RESC1608X55N 166.561,137.81 r0 bottom
R28 "1" RESC1608X55N 164.5,136 r0 bottom
R29 "1" RESC1608X55N 155.946,134.5 r270 bottom
R30 "1" RESC1608X55N 164.5,134 r0 bottom
R31 "10M" RESC2012X60N 103.346,129.294 r0 bottom
R32 "100" RESC1608X55N 106.401,132 r90 bottom
R33 "1" RESC1608X55N 156,130.5 r90 bottom
R34 "10M" RESC2012X60N 103.346,126.682 r0 bottom
R35 "100" RESC1608X55N 106.401,124.19 r270 bottom
R36 "100" RESC1608X55N 155.5,122 r180 bottom
R37 "0R1" RESC2012X60N 146,117 r180 bottom
R38 "0R1" RESC2012X60N 142,116.975 r0 bottom
R39 "499" RESC1608X55N 108.941,126.73 r0 bottom
R40 "499" RESC1608X55N 111.363,125.095 r0 bottom
R41 "499" RESC1608X55N 108.941,129.294 r0 bottom
R42 "499" RESC1608X55N 111.363,130.969 r0 bottom
RN1 "10k" RN_YAGEO_TC164 119.99,144.915 r0 bottom
RN2 "RN_VISHAY_1446-321806" SBDIP16-300 150,134 r0 bottom locked value="20k 3k5"
RN3 "10k" RN_YAGEO_TC164 120,140.5 r0 bottom
RN4 "RN_VISHAY_1446-321806" SBDIP16-300 167.5,117 r90 bottom value="20k 3k5"
RR1 "PT1000 SMD 1206 fd F 0,3" DFN310X150X55-2N 176.505,123.325 r180 bottom
T1 "MMBF4392L" SOT95P240X110-3N 121.271,107 r270 top
T2 "MMBT3904" SOT95P230X110-3N 120.332,106.68 r270 bottom

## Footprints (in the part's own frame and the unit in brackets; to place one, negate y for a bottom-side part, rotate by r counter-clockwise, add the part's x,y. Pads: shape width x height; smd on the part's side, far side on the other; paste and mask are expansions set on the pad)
CAPC1005X55N [mm] "Capacitor, Non-Polarized, Chip; 1.00mm L X 0.50mm W X 0.70mm H, IPC Medium Density"
  rect 0.62x0.62 smd: 1(-0.45,0) 2(0.45,0)
  body extent -0.52,-0.27 0.53,0.28, height 0.55
CAPC1608X87N [mm] "Chip Capacitor, Body 1.6x0.8mm IPC Medium Density"
  rect 0.95x1 smd: 1(-0.8,0) 2(0.8,0)
  body extent -0.87,-0.47 0.88,0.48, height 0.87
CAPC2012X95N [mm] "Chip Capacitor, Body 2.0x1.25mm, IPC Medium Density"
  rect 1.1x1.45 smd: 1(-0.9,0) 2(0.9,0)
  silkscreen extent 0,-0.58 0,0.58, body extent -1.05,-0.67 1.05,0.68, height 0.95
CAPC2012X135N [mm] "Chip Capacitor, Body 2.0x1.25mm, IPC Medium Density"
  rect 1.05x1.4 smd: 1(-0.9,0) 2(0.9,0)
  silkscreen extent 0,-0.58 0,0.58, body extent -1.05,-0.67 1.05,0.68, height 1.25
CAPC_MURATA_NFM3DC_1206 [mm] "EMIFIL Chip Capacitor, Body 3.2x1.25mm, MURATA NFM3DC Serie"
  rect 0.95x1 smd: 1(-1.725,0) 3(1.725,0)
  rect 1x0.7 smd: 2(0,-0.65) 2(0,0.65)
  silkscreen extent -1.7,-0.82 1.7,0.82, body extent -1.7,-0.72 1.7,0.73, height 0.9
CAPC_MURATA_NFM21PC_0805 [mm] "EMIFIL Chip Capacitor, Body 2.0x1.25mm, MURATA NFM21PC Serie"
  rect 0.6x0.8 smd: 1(-1,0) 3(1,0)
  rect 0.6x0.65 smd: 2(0,-0.625) 2(0,0.625)
  Top Layer region: -0.3,0.95 0.3,0.95 0.3,-0.95 -0.3,-0.95
  silkscreen extent -1.1,-0.7 1.1,0.7, body extent -1.1,-0.67 1.1,0.68, height 0.95
DFN310X150X55-2N [mm] "DFN; 2 Pin,3.10mm L X 1.50mm W X 0.40mm H, IPC Medium Density"
  rect 0.6x1.7 smd: 1(-1.35,0) 2(1.35,0)
  silkscreen extent -0.55,-0.75 0.55,0.75, body extent -1.55,-0.75 1.55,0.75, height 0.55
FIDUCIAL_TOP_C100-200 [mm] "Round Fiducial Target, Top Layer, 1.0mm, Top Solder 2.0mm, Keepout =2.0mm"
  round 1 smd paste-0.51 mask+0.5: FTG2(0,0)
  Top Layer keep-out circle w0.1: c0,0 r1
IND_WURTH_WE-SL2 [mm] "Common Mode SMD Line Filter WE-SL2"
  rect 2x1.2 smd: 1(-3.75,1.27) 2(-3.75,-1.27) 3(3.75,-1.27) 4(3.75,1.27)
  silkscreen extent -4.75,-3.15 4.75,3.15, body extent -4.75,-3.15 4.75,3.15, height 5.3
INDC1608X95N [mm] "Chip Inductor, 2-Leads, EIA 0603, Metric 1608, Body 1.6x0.8mm, IPC Medium Density"
  rect 0.95x1 smd: 1(-0.8,0) 2(0.8,0)
  body extent -0.87,-0.47 0.88,0.48, height 0.95
LEMO_EXG.0B.302.HLN [mm] "Size 0B, 2 Female Contacts Elbow Receptacle (90°) With Alignment Key and Two Nuts (For Back Panel Mounting)"
  round 1.7 hole 1: 1(-1.27,-1.27) 2(-1.27,1.27) 3(-3.81,3.81) 3(-3.81,-3.81) 3(3.81,3.81) 3(3.81,-3.81)
  silkscreen extent -6.59,-6.25 18.41,6.25, body extent -6.59,-6.25 18.41,6.25, height 12.95
MSBOX_PERANCEA_PFL9T [mm] "Metal Screening Box, Internal dimensions L75 x W50 x H15mm, Overall Size 80x55x16mm"
  round 2.1 hole 1.6: 1(-30,25.5) 2(-10,25.5) 3(10,25.5) 4(30,25.5) 5(38,10) 6(38,-10) 7(30,-25.5) 8(10,-25.5) 9(-10,-25.5) 10(-30,-25.5) 11(-38,-10) 12(-38,10)
  silkscreen extent -38.5,-26 38.5,26, body extent -39.94,-27.43 39.94,27.43, height 15.6
MTG270_500 [mm] "Plated Through Hole: Hole Dia.=2.7mm Pad Dia.=5.0mm"
  round 5 hole 2.7: 1(0,0)
OSC_ABRACON_AMPMD [mm] "4 Pins, 2.5x2.0mm, Power Optimized MEMS Oscillator, AMPMD Series, CMOS"
  rect 0.8x0.7 smd: 1(-0.625,0.825) 2(-0.625,-0.825) 3(0.625,-0.825) 4(0.625,0.825)
  silkscreen extent -1.62,-0.13 1,0.95, body extent -1,-1.25 1,1.25, height 0.81
RES_VISHAY_Z203 [mm] "Resistor, Radial Rectangular, Leads Spacing 3.81mm - Body 7.62mm X 2.67mm"
  round 1.6 hole 0.9: 1(-1.905,0) 2(1.905,0)
  silkscreen extent -3.81,-1.33 3.81,1.33, body extent -3.81,-1.33 3.81,1.34, height 8.53
RESC1005X40N [mm] "Chip Resistor, EIA 0402, Metric 1005, Body 1.0x0.5mm, IPC Medium Density"
  rect 0.58x0.62 smd: 1(-0.47,0) 2(0.47,0)
  body extent -0.52,-0.27 0.53,0.28, height 0.4
RESC1608X55N [mm] "Chip Resistor, EIA 0603, Metric 1608, Body 1.6x0.8mm, IPC Medium Density"
  rect 0.9x1 smd: 1(-0.8,0) 2(0.8,0)
  body extent -0.87,-0.47 0.88,0.48, height 0.55
RESC2012X60N [mm] "Chip Resistor, EIA 0805, Metric 2012, Body 2.0x1.2mm, IPC Medium Density"
  rect 0.95x1.4 smd: 1(-1,0) 2(1,0)
  silkscreen extent 0,-0.55 0,0.55, body extent -1.1,-0.67 1.1,0.68, height 0.6
RN_YAGEO_TC164 [mm] "Resistor, Chip Array, Concave, Pitch 0.80mm, 8 pin,1.60mm W X 3.20mm L X 0.70mm H, Type TC164, IPC Medium Density"
  rect 0.9x0.55 smd: 1(-0.9,1.2) 2(-0.9,0.4) 3(-0.9,-0.4) 4(-0.9,-1.2) 5(0.9,-1.2) 6(0.9,-0.4) 7(0.9,0.4) 8(0.9,1.2)
  silkscreen extent -1.92,-1.75 0,1.75, body extent -0.8,-1.65 0.8,1.65, height 0.7
SAMTEC_FTSH-110-01-F-DV-K [mm] "20 Contacts, Pitch 1.27mm, Dual Row Straight Shrouded SMT Micro Header with Keying Shroud"
  rect 0.74x2.79 smd: 1(-5.715,-2.035) 2(-5.715,2.029) 3(-4.445,-2.035) 4(-4.445,2.029) 5(-3.175,-2.035) 6(-3.175,2.029) 7(-1.905,-2.035) 8(-1.905,2.029) 9(-0.635,-2.035) 10(-0.635,2.029) 11(0.635,-2.035) 12(0.635,2.029) 13(1.905,-2.035) 14(1.905,2.029) 15(3.175,-2.035) 16(3.175,2.029) 17(4.445,-2.035) 18(4.445,2.029) 19(5.715,-2.035) 20(5.715,2.029)
  silkscreen extent -6.8,-3.78 6.35,3.78, body extent -6.35,-2.92 6.35,2.92, height 6.12
SBDIP16-300 [mm] "Side-Brazed Ceramic Dual In-Line Package (SBDIP) 16 Leads, Row Spacing 7.62 mm; Pitch 2.54 mm"
  rect 1.5x1.5 hole 0.9: 1(-3.81,8.89)
  round 1.5 hole 0.9: 2(-3.81,6.35) 3(-3.81,3.81) 4(-3.81,1.27) 5(-3.81,-1.27) 6(-3.81,-3.81) 7(-3.81,-6.35) 8(-3.81,-8.89) 9(3.81,-8.89) 10(3.81,-6.35) 11(3.81,-3.81) 12(3.81,-1.27) 13(3.81,1.27) 14(3.81,3.81) 15(3.81,6.35) 16(3.81,8.89)
  silkscreen extent -2.65,-10.3 2.65,10.3, body extent -4.12,-10.28 4.13,10.29, height 4.55
SODFL2512X100N [mm] "SODFL Diode; 1.70mm W X 1.25mm L X 1.00mm H body, IPC Medium Density"
  rect 0.84x0.46 smd: 1(-1.14,0) 2(1.14,0)
  silkscreen extent -1.47,-0.65 0.85,0.86, body extent -1.35,-0.65 1.35,0.65, height 1
SOIC127P600X175-8N [mm] "SOIC 8, Pitch 1.27mm - Body 4x5mm, IPC Medium Density"
  rect 1.55x0.6 smd: 1(-2.7,1.905) 2(-2.7,0.635) 3(-2.7,-0.635) 4(-2.7,-1.905) 5(2.7,-1.905) 6(2.7,-0.635) 7(2.7,0.635) 8(2.7,1.905)
  silkscreen extent -2.52,-2.5 1.55,2.88, body extent -3.1,-2.5 3.1,2.5, height 1.75
SOP65P490X110-8N [mm] "SOP, 0.65mm pitch; 8 pin, 3.00mm W X 3.00mm L X 1.10mm H body, IPC Medium Density"
  rect 1.5x0.45 smd: 1(-2.2,0.975) 2(-2.2,0.325) 3(-2.2,-0.325) 4(-2.2,-0.975) 5(2.2,-0.975) 6(2.2,-0.325) 7(2.2,0.325) 8(2.2,0.975)
  silkscreen extent -2.83,-1.5 1.12,1.82, body extent -2.45,-1.55 2.45,1.55, height 1.1
SOP65P640X120-16N [mm] "SOP, 0.65mm pitch; 16 pin, 4.40mm W X 5.00mm L X 1.20mm H body IPC Medium Density"
  rect 1.45x0.45 smd: 1(-2.95,2.275) 2(-2.95,1.625) 3(-2.95,0.975) 4(-2.95,0.325) 5(-2.95,-0.325) 6(-2.95,-0.975) 7(-2.95,-1.625) 8(-2.95,-2.275) 9(2.95,-2.275) 10(2.95,-1.625) 11(2.95,-0.975) 12(2.95,-0.325) 13(2.95,0.325) 14(2.95,0.975) 15(2.95,1.625) 16(2.95,2.275)
  silkscreen extent -3.07,-2.55 1.85,3.17, body extent -3.12,-2.55 3.12,2.55, height 1.2
SOP65P640X120-24N [mm] "SOP, 0.65mm Pitch; 24 Pin, 4.40mm W X 7.80mm L X 1.20mm H Body, IPC Medium Density"
  rect 1.5x0.45 smd: 1(-2.9,3.575) 2(-2.9,2.925) 3(-2.9,2.275) 4(-2.9,1.625) 5(-2.9,0.975) 6(-2.9,0.325) 7(-2.9,-0.325) 8(-2.9,-0.975) 9(-2.9,-1.625) 10(-2.9,-2.275) 11(-2.9,-2.925) 12(-2.9,-3.575) 13(2.9,-3.575) 14(2.9,-2.925) 15(2.9,-2.275) 16(2.9,-1.625) 17(2.9,-0.975) 18(2.9,-0.325) 19(2.9,0.325) 20(2.9,0.975) 21(2.9,1.625) 22(2.9,2.275) 23(2.9,2.925) 24(2.9,3.575)
  silkscreen extent -2.11,-3.9 1.83,4.54, body extent -3.12,-3.95 3.12,3.95, height 1.2
SOT95P230X110-3N [mm] "SOT23, 3 pin, Pitch 0.95mm - 1.3mm W X 2.9mm L X 1.1mm H, IPC Medium Density"
  rect 1x0.6 smd: 1(-1.15,0.95) 2(-1.15,-0.95) 3(1.15,0)
  silkscreen extent -1.24,-1.45 0.33,1.87, body extent -1.08,-1.5 1.25,1.5, height 1.1
SOT95P240X110-3N [mm] "SOT23 3-Leads, Pitch 0.95mm, Body 1.3x2.9mm, IPC Medium Density"
  rect 1.05x0.65 smd: 1(-1.15,0.95) 2(-1.15,-0.95) 3(1.15,0)
  silkscreen extent -1.52,-1.45 0.3,1.92, body extent -1.25,-1.5 1.25,1.5, height 1.1
SOT95P280X145-5N [mm] "SOT, 0.95mm pitch; 5 pin, 1.60mm W X 2.90mm L X 1.45mm H body, IPC Medium Density"
  rect 1.1x0.6 smd: 1(-1.3,0.95) 2(-1.3,0) 3(-1.3,-0.95) 4(1.3,-0.95) 5(1.3,0.95)
  silkscreen extent -2.53,-1.45 0.43,1.45, body extent -1.4,-1.5 1.4,1.5, height 1.45
TO-99 [mm] "TO-99, 8 Leads, Body Dia. 9.4mm (max)"
  round 1.5 hole 0.8: 1(1.796,1.796) 2(0,2.54) 3(-1.796,1.796) 4(-2.54,0) 5(-1.796,-1.796) 6(0,-2.54) 7(1.796,-1.796) 8(2.54,0)
  silkscreen extent -4.7,-4.7 5.84,4.7, body extent -4.7,-4.7 5.84,4.7, height 5.72
TRIM_BOURNS_3269W [mm] "Bourns 3314G-1 Bourns 3269W Trimming Potentiometer (Top Adjust)"
  rect 1.19x2.79 smd: 1(-2.54,-2.415) 2(0,2.415) 3(2.54,-2.415)
  silkscreen extent -3.44,-2.13 3.42,2.19, body extent -3.44,-3.24 3.42,3.24, height 8.46

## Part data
B1 B2 B3 B4 B5 B6 B7 B8 B9 B10: library part PLATED_HOLE2.7_PAD5.0, "Single Terminal Socket"
C1 C8 C54 C66: library part CC0603_10NF_50V_5%_C0G, "Non-polarised capacitor", Case=0603, Manufacturer=GENERIC, Manufacturer1 ComponentHeight=0.9mm, Manufacturer1 Example=TDK, Manufacturer1 Part Number=C1608C0G1H103J080, Tolerance=±5%, Voltage=50V
C2 C3 C4 C5 C6 C9 C11 C12 C14 C15 C16 C17 C19 C20 C22 C23 C24 C25 C26 C27 C28 C29 C31 C34 C37 C38 C45 C46 C47 C49 C50 C51 C52 C55 C59 C61 C62 C63 C65 C67 C71 C72 C73 C74 C75 C76 C78 C79 C80 C82 C83: library part CC0402_100NF_50V_10%_X7R, "Non-polarised capacitor", Case=0402, Manufacturer=GENERIC, Manufacturer1 ComponentHeight=0.55mm, Manufacturer1 Example=MURATA, Manufacturer1 Part Number=GRM155R71H104KE14D, Tolerance=±10%, Voltage=50V
C7 C21 C39 C41 C44 C77: library part CC0805_10UF_25V_10%_X5R, "Non-polarised capacitor", Case=0805, Manufacturer=GENERIC, Manufacturer1 ComponentHeight=0.95mm, Manufacturer1 Example=MURATA, Manufacturer1 Part Number=GRM219R61E106KA12D, Tolerance=±10%, Voltage=25V
C10 C13 C18: library part CEMIF_2.2UF_6.3V_MURATA_NFM21PC225B0J3, "EMI Filter - Capacitor Type 1", Case=0805, Manufacturer=MURATA, Manufacturer Part Number=NFM21PC225B0J3, Tolerance=±20%, Voltage=6.3V
C30 C32 C33 C35 C36 C57 C60 C86 C87: library part CC0805_47NF_25V_5%_C0G, "Non-polarised capacitor", Case=0805, Manufacturer=GENERIC, Manufacturer1 ComponentHeight=1.4mm, Manufacturer1 Example=KEMET, Manufacturer1 Part Number=C0805C473J3GACTU, Tolerance=±5%, Voltage=25V
C40 C42 C43 C48 C53 C64: library part CEMIF_22NF_50V_MURATA_NFM3DCC223R1H3L, "EMI Filter - Capacitor Type 1", Case=1205, Manufacturer=MURATA, Manufacturer Part Number=NFM3DCC223R1H3L, Tolerance=+50%-20%, Voltage=50V
C56 C58 C68 C69: library part CC0402_1UF_16V_10%_X5R, "Non-polarised capacitor", Case=0402, Manufacturer=GENERIC, Manufacturer1 ComponentHeight=0.55mm, Manufacturer1 Example=TDK, Manufacturer1 Part Number=C1005X5R1C105KT, Tolerance=±10%, Voltage=16V
C70 C81: library part CC0805_1NF_50V_5%_C0G, "Non-polarised capacitor", Case=0805, Manufacturer=GENERIC, Manufacturer1 ComponentHeight=0.88mm, Manufacturer1 Example=KEMET, Manufacturer1 Part Number=C0805C102J5GACTU, Tolerance=±5%, Voltage=50V
C84 C85 C88 C89 C90 C91: library part CC0402_100PF_25V_1%_C0G_KEMET_HiQ-CBR, "Non-polarised capacitor", Case=0402, Manufacturer=KEMET, Manufacturer Part Number=CBR04C101F3GAC, Tolerance=±1%, Voltage=25V
D1 D2 D3: "Diode", Case=SOD-323F, Manufacturer="FAIRCHILD SEMICONDUCTOR", Power=150mA, Voltage=75V
FTG1 FTG2 FTG3 FTG4 FTG5 FTG6: library part FIDUCIAL_TARGET_C100-200, "Fiducial Target"
IC1 IC3: "2.1 Ohm On Resistance, ±15 V/+12 V/±5 V  iCMOS SPDT Switch", Case=MSOP8, Manufacturer="ANALOG DEVICES", Manufacturer Part Number=ADG1419BRM
IC2: "Programmable Resolution 1-Wire Digital Thermometer", Case=uSOP8, Manufacturer="DALLAS MAXIM", Manufacturer Part Number=DS18B20U
IC4 IC7 IC9 IC14 IC20: "Operational Amplifier", Case=SOT23-5, Manufacturer="ANALOG DEVICES"
IC5 IC8 IC19: "Operational Amplifier", Case=MSOP8, Manufacturer="ANALOG DEVICES", Manufacturer Part Number=ADA4522-1ARM
IC6 IC17: library part OPA388IDGKT, "Operational Amplifier", Case=MSOP8, Manufacturer="TEXAS INSTRUMENTS"
IC10: "32-Bit, 10 kSPS, Sigma-Delta ADC with 100 µs Settling and True Rail-to-Rail Buffers", Case=TSSOP24, Manufacturer="ANALOG DEVICES", Manufacturer Part Number=AD7177-2BRU
IC11 IC15: library part OPA189IDGKR, "Operational Amplifier", Case=MSOP8, Manufacturer="TEXAS INSTRUMENTS"
IC12 IC16 IC21 IC24: "High-Speed Differential Line Receiver", Case=SOT23-5, Manufacturer="TEXAS INSTRUMENTS"
IC13 IC18: "8-Channel, ±15 V/+12 V/±5 V iCMOS Multiplexers", Case=TSSOP16, Manufacturer="ANALOG DEVICES", Manufacturer Part Number=ADG1408YRU
IC22: "Oven-Controlled, Buried Zener, 6.62V Voltage Reference", Case=TO-99, Manufacturer="ANALOG DEVICES", Manufacturer Part Number=ADR1000AH
IC23: "Dual Operational Amplifier", Case=SOIC8, Manufacturer="TEXAS INSTRUMENTS"
IC25 IC26: "High-Speed Differential Line Driver", Case=SOT23-5, Manufacturer="TEXAS INSTRUMENTS", Manufacturer Part Number=SN65LVDS1DBV
J1 J3: library part SAMTEC_FTSH-110-01-F-DV-K, "Connector 20 Male", Manufacturer=SAMTEC, Manufacturer Part Number=FTSH-110-01-F-DV-K
J2: library part LEMO_EXG.0B.302.HLN, Manufacturer=LEMO, Manufacturer Part Number=EXG.0B.302.HLN
L1 L2 L3 L4 L5 L6 L7 L8 L9 L10 L11 L12 L13 L14 L15 L16 L18 L19 L20 L21: library part IND0603_MURATA_BLM18HE102SN1, Case=0603, Manufacturer=MURATA, Manufacturer Part Number=BLM18HE102SN1, Power=600mA, Resistance=0.35R, Tolerance=±25%
L17: library part IND_10UH_50%_WURTH_WE-SL2-744226, "Inductor Common Mode", Manufacturer="WURTH ELEKTRONIK", Manufacturer Part Number=744226, Power=1.6A, Resistance=0.08R, Tolerance=±30%
MSBOX1: library part MSBOX_PERANCEA_PFL9T, Manufacturer=PERANCEA, Manufacturer Part Number=PFL9T
OSC1: library part OSC_16MHZ_ABRACON_AMPMDFB-16.0000, "Oscillator 4 pins 1=OE 2=GND 3=OUT 4=VDD", Manufacturer=ABRACON, Manufacturer Part Number=AMPMDFB-16.0000
P1 P2: library part TRIM_12T_10R_BOURNS_3269W-1-100GLF, "Trimming Potentiometer", Case=3269W, Manufacturer=BOURNS, Manufacturer Part Number=3269W-1-100GLF, Power=0.25W, Tolerance=±10%
R1 R2 R5 R6 R28 R29 R30 R33: library part R0603_1R_1%_0.1W_50PPM_VISHAY_MCT, "Resistor - 1%", Case=0603, Manufacturer="VISHAY BEYSCHLAG", Manufacturer Part Number=MCT06030C1008F, Power=0.1W, Tolerance=±1%
R3 R16 R17 R19 R20 R22 R27: library part R0603_1K_0.1%_0.063W_10PPM, "Resistor - 0.1%", Case=0603, Manufacturer=GENERIC, Manufacturer1 ComponentHeight=0.55mm, Manufacturer1 Example="TYCO HOLSWORTHY", Manufacturer1 Part Number=RN73C1J1K0BTG, Power=0.063W, Tolerance=±0.1%
R4 R18: library part R0402_10K_1%_0.0625W_100PPM, "Resistor - 1%", Case=0402, Manufacturer=GENERIC, Manufacturer1 ComponentHeight=0.4mm, Manufacturer1 Example="YAGEO PHYCOMP", Manufacturer1 Part Number=232270671003L, Power=0.0625W, Tolerance=±1%
R7 R8 R14 R24 R26: library part R0603_10R_0.1%_0.063W_10PPM, "Resistor - 0.1%", Case=0603, Manufacturer=GENERIC, Manufacturer1 ComponentHeight=0.5mm, Manufacturer1 Example="TYCO HOLSWORTHY", Manufacturer1 Part Number=RN73C1J10RBTDF, Power=0.063W, Tolerance=±0.1%
R9: library part RF0_20K_0.01%_0.6W_0.5PPM_VISHAY_Z203, "Resistor - 0.01%", Case="LS3.81 W2.67 x L7.62 x H8.53", Manufacturer="VISHAY FOIL RESISTOR", Manufacturer Part Number=Y144520K0000T, Power=0.6W, Tolerance=±0.01%
R10: library part RF0_120R_0.01%_0.6W_0.5PPM_VISHAY_Z203, "Resistor - 0.01%", Case="LS3.81 W2.67 x L7.62 x H8.53", Manufacturer="VISHAY FOIL RESISTOR", Manufacturer Part Number=Y1445120R000T, Power=0.6W, Tolerance=±0.01%
R11: library part RF0_1K_0.01%_0.6W_0.5PPM_VISHAY_Z203, "Resistor - 0.01%", Case="LS3.81 W2.67 x L7.62 x H8.53", Manufacturer="VISHAY FOIL RESISTOR", Manufacturer Part Number=Y14451K00000T, Power=0.6W, Tolerance=±0.01%
R12: library part RF0_68K_0.01%_0.6W_0.5PPM_VISHAY_Z203, "Resistor - 0.01%", Case="LS3.81 W2.67 x L7.62 x H8.53", Manufacturer="VISHAY FOIL RESISTOR", Manufacturer Part Number=Y144568K0000T, Power=0.6W, Tolerance=±0.01%
R13: library part RF0_12K_0.01%_0.6W_0.5PPM_VISHAY_Z203, "Resistor - 0.01%", Case="LS3.81 W2.67 x L7.62 x H8.53", Manufacturer="VISHAY FOIL RESISTOR", Manufacturer Part Number=Y144512K0000T, Power=0.6W, Tolerance=±0.01%
R15 R25 R32 R35 R36: library part R0603_100R_0.1%_0.063W_10PPM, "Resistor - 0.1%", Case=0603, Manufacturer=GENERIC, Manufacturer1 ComponentHeight=0.5mm, Manufacturer1 Example="TYCO HOLSWORTHY", Manufacturer1 Part Number=RN73C1J100RBTDF, Power=0.063W, Tolerance=±0.1%
R21: library part R0402_330K_1%_0.0625W_100PPM, "Resistor - 1%", Case=0402, Manufacturer=GENERIC, Manufacturer1 ComponentHeight=0.4mm, Manufacturer1 Example="YAGEO PHYCOMP", Manufacturer1 Part Number=232270673304L, Power=0.0625W, Tolerance=±1%
R23: library part R0603_100K_0.1%_0.063W_10PPM, "Resistor - 0.1%", Case=0603, Manufacturer=GENERIC, Manufacturer1 ComponentHeight=0.55mm, Manufacturer1 Example="TYCO HOLSWORTHY", Manufacturer1 Part Number=RN73C1J100KBTDF, Power=0.063W, Tolerance=±0.1%
R31 R34: library part R0805_10M_1%_0.125W_100PPM, "Resistor - 1%", Case=0805, Manufacturer=GENERIC, Manufacturer1 ComponentHeight=0.6mm, Manufacturer1 Example="NIC COMPONENT", Manufacturer1 Part Number=NRC10F1005TRF, Power=0.125W, Tolerance=±1%
R37 R38: library part R0805_0R1_1%_0.25W_75PPM_VISHAY_WSL18, "Resistor - 1%", Case=0805, Manufacturer="VISHAY DALE", Manufacturer Part Number=WSL0805R1000FEA18, Power=0.25W, Tolerance=±1%
R39 R40 R41 R42: library part R0603_499R_0.1%_0.063W_10PPM, "Resistor - 0.1%", Case=0603, Manufacturer=GENERIC, Manufacturer1 ComponentHeight=0.5mm, Manufacturer1 Example="TYCO HOLSWORTHY", Manufacturer1 Part Number=RN73C1J499RBTDF, Power=0.063W, Tolerance=±0.1%
RN1 RN3: library part RN_10K_YAGEO_TC164-FR-0710KL, "DIL8 Resistor Network 4 Isolated Resistor 1%", Case=1206, Manufacturer=YAGEO, Manufacturer Part Number=TC164-FR-0710KL, Power=0.062W, Tolerance=±1%
RN2 RN4: "8 Isolated Resistors Through-Hole Resistor Array", Case=DIP16-300, Manufacturer=VISHAY, Manufacturer Part Number="1446 Model, Custom Number: 321806", Power=0.1W, Tolerance=±0.01%
RR1: "2 Pin Temperature Sensor", Case=DFN2, Manufacturer="UMWELTSENSORTECHNIK GmbH (UST)"
T1: "N-Channel JFET", Case=SOT23-3, Manufacturer="ON SEMICONDUCTOR"
T2: "NPN Transistor", Case=SOT23-3, Manufacturer=NEXPERIA

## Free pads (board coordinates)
  round 3.5 on Mech9: 1(97.6,90.1) 1(324.8,90.1)
  round 2 on Mech9: 1(107.6,90.1) 1(314.8,90.1) 1(314.8,234.3)
  round 0.8 on Mech9: 1(125,100) 1(125,156) 1(125,168.4) 1(125,224.4) 1(126.25,100) 1(126.25,156) 1(126.25,168.4) 1(126.25,224.4) 1(127.5,100) 1(127.5,156) 1(127.5,168.4) 1(127.5,224.4) 1(128.75,100) 1(128.75,156) 1(128.75,168.4) 1(128.75,224.4) 1(130,100) 1(130,156) 1(130,168.4) 1(130,224.4) 1(175,100) 1(175,156) 1(175,168.4) 1(175,224.4) 1(176.25,100) 1(176.25,156) 1(176.25,168.4) 1(176.25,224.4) 1(177.5,100) 1(177.5,156) 1(177.5,168.4) 1(177.5,224.4) 1(178.75,100) 1(178.75,156) 1(178.75,168.4) 1(178.75,224.4) 1(180,100) 1(180,156) 1(180,168.4) 1(180,224.4) 1(242.4,100) 1(242.4,156) 1(242.4,168.4) 1(242.4,224.4) 1(243.65,100) 1(243.65,156) 1(243.65,168.4) 1(243.65,224.4) 1(244.9,100) 1(244.9,156) 1(244.9,168.4) 1(244.9,224.4) 1(246.15,100) 1(246.15,156) 1(246.15,168.4) 1(246.15,224.4) 1(247.4,100) 1(247.4,156) 1(247.4,168.4) 1(247.4,224.4) 1(292.4,100) 1(292.4,156) 1(292.4,168.4) 1(292.4,224.4) 1(293.65,100) 1(293.65,156) 1(293.65,168.4) 1(293.65,224.4) 1(294.9,100) 1(294.9,156) 1(294.9,168.4) 1(294.9,224.4) 1(296.15,100) 1(296.15,156) 1(296.15,168.4) 1(296.15,224.4) 1(297.4,100) 1(297.4,156) 1(297.4,168.4) 1(297.4,224.4)

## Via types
v1: diameter 0.5, hole 0.2, Top Layer to Bottom Layer, tented both sides, 477 vias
